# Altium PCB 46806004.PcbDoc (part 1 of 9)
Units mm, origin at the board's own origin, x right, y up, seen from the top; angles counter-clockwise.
Board outline 130 x 105 mm, 8 copper layers (Top Layer, P1-GND, L1-Signal, L2-Signal, L3-Signal, L4-Signal, P2-GND, Bottom Layer), stack 1.63 mm thick; 796 components, 496 nets, 2808 pads, 1195 vias.
Unrouted connection lines stored in the file: 1.
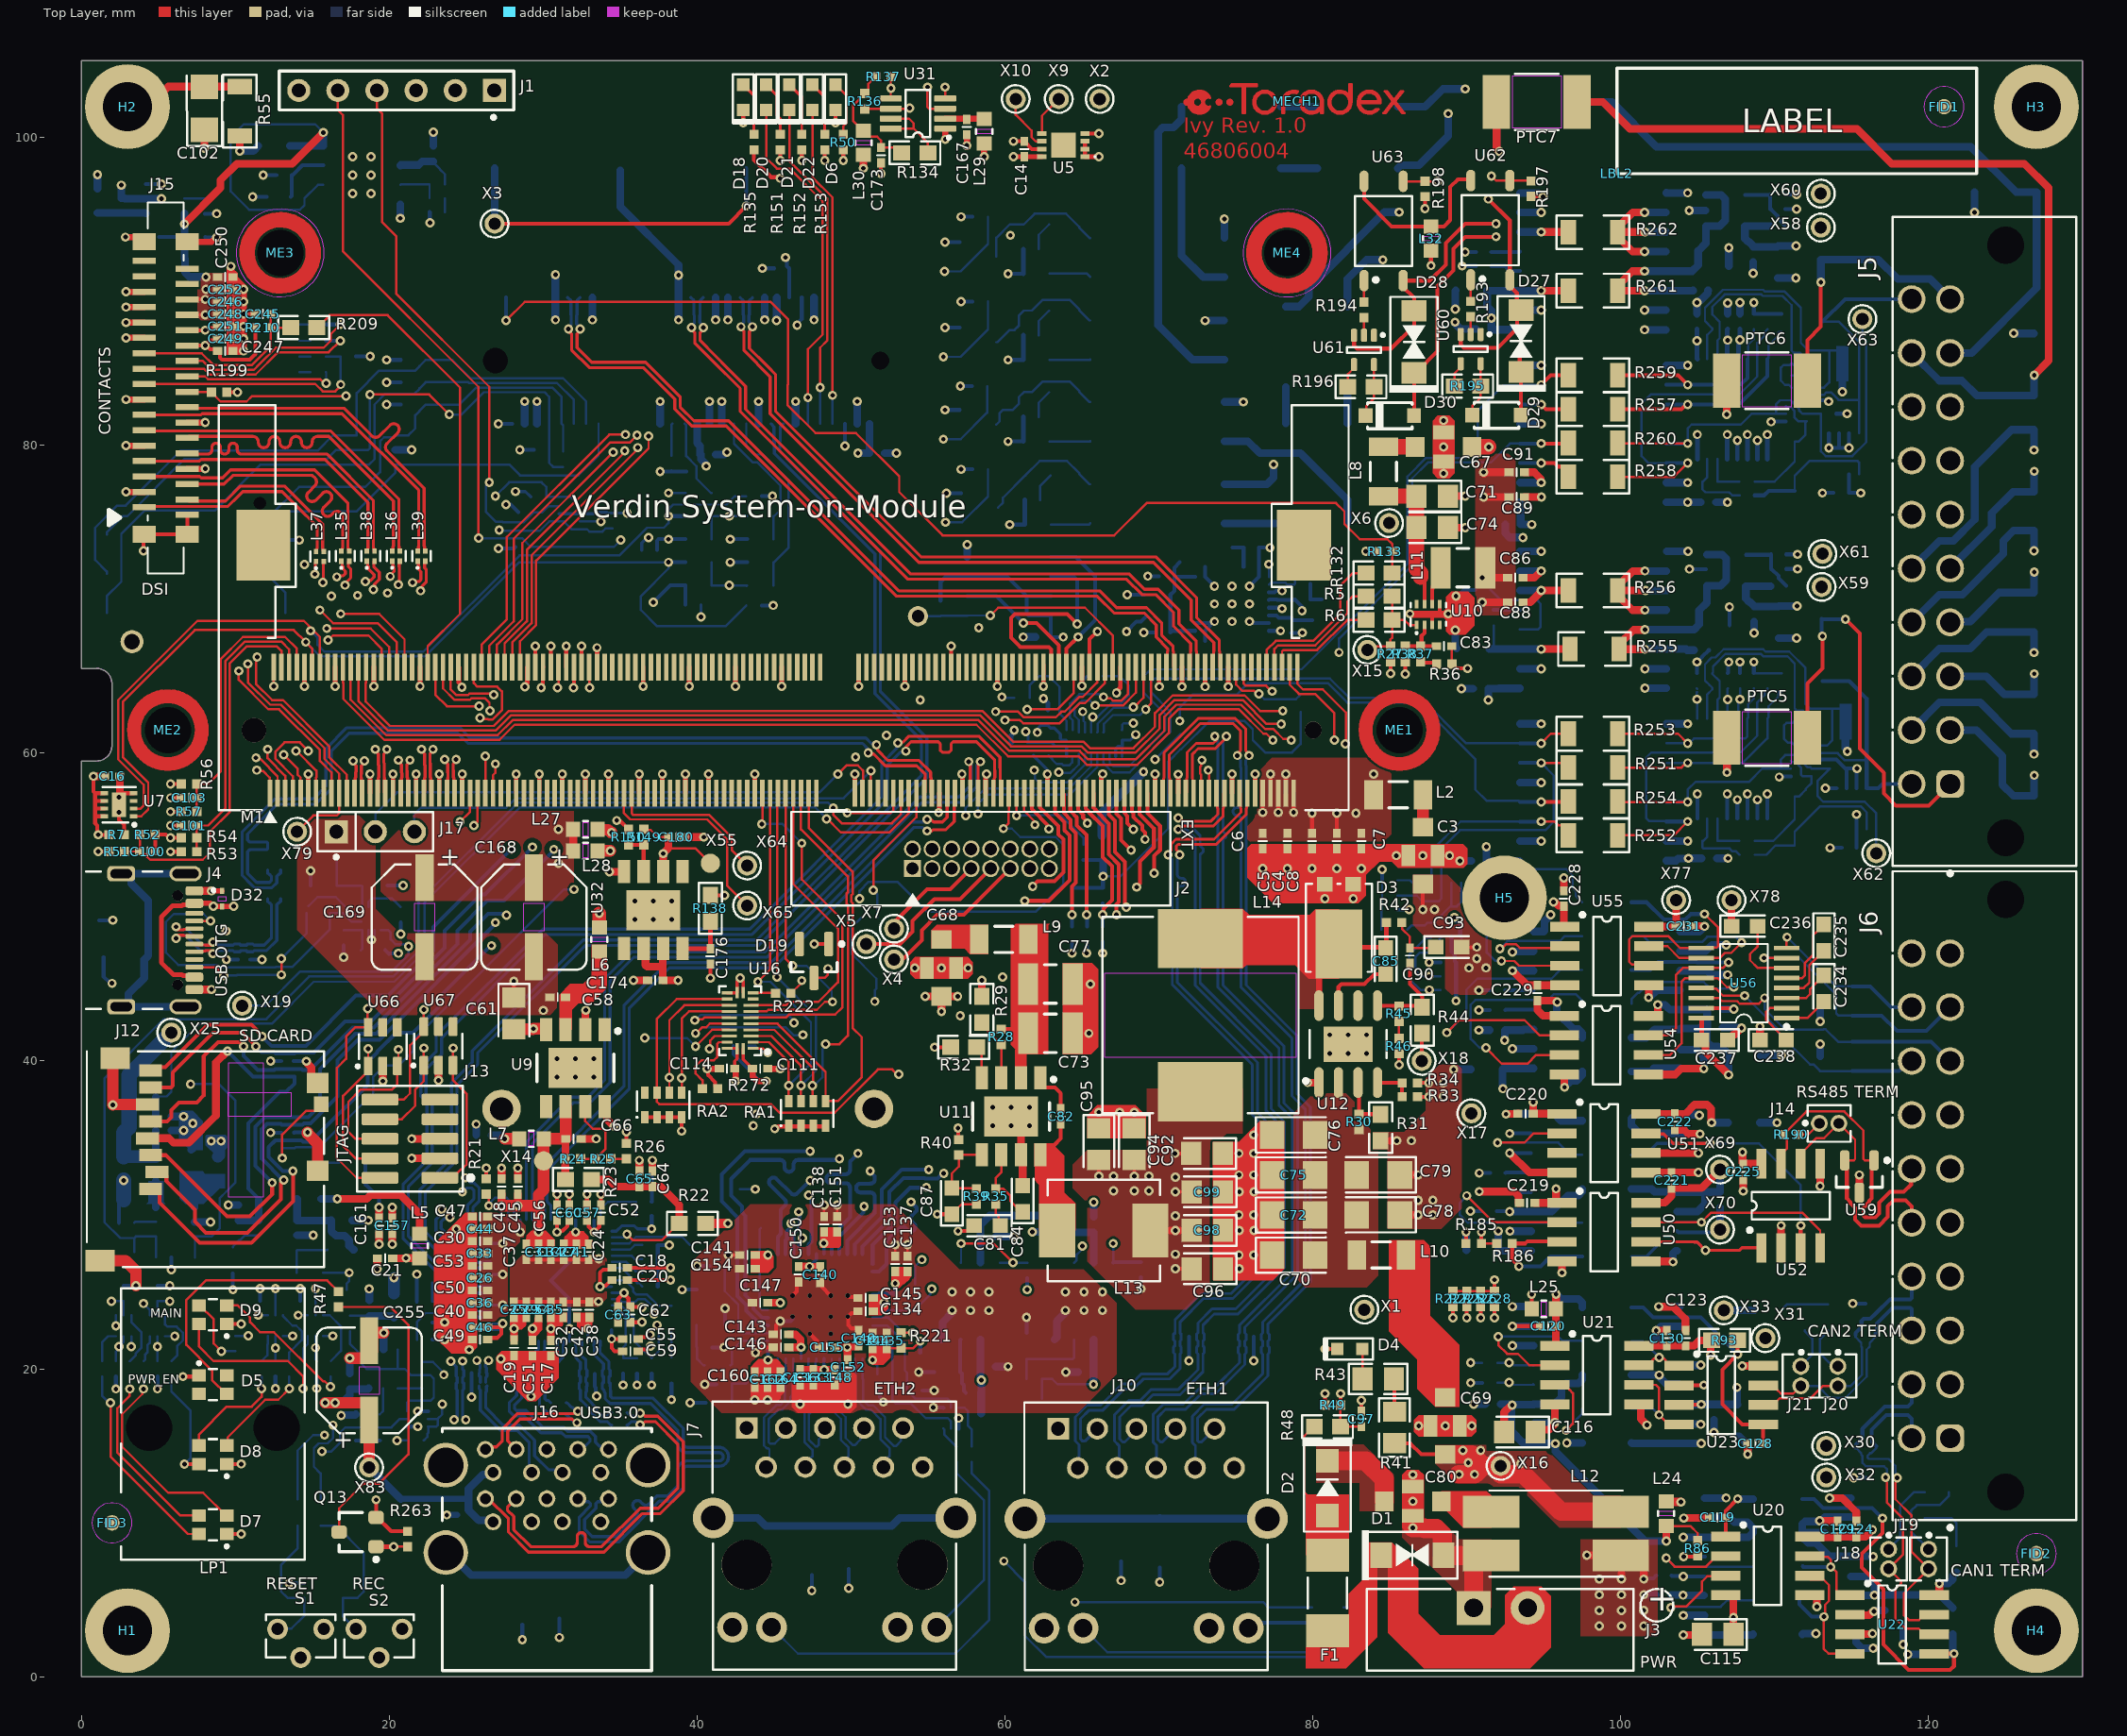
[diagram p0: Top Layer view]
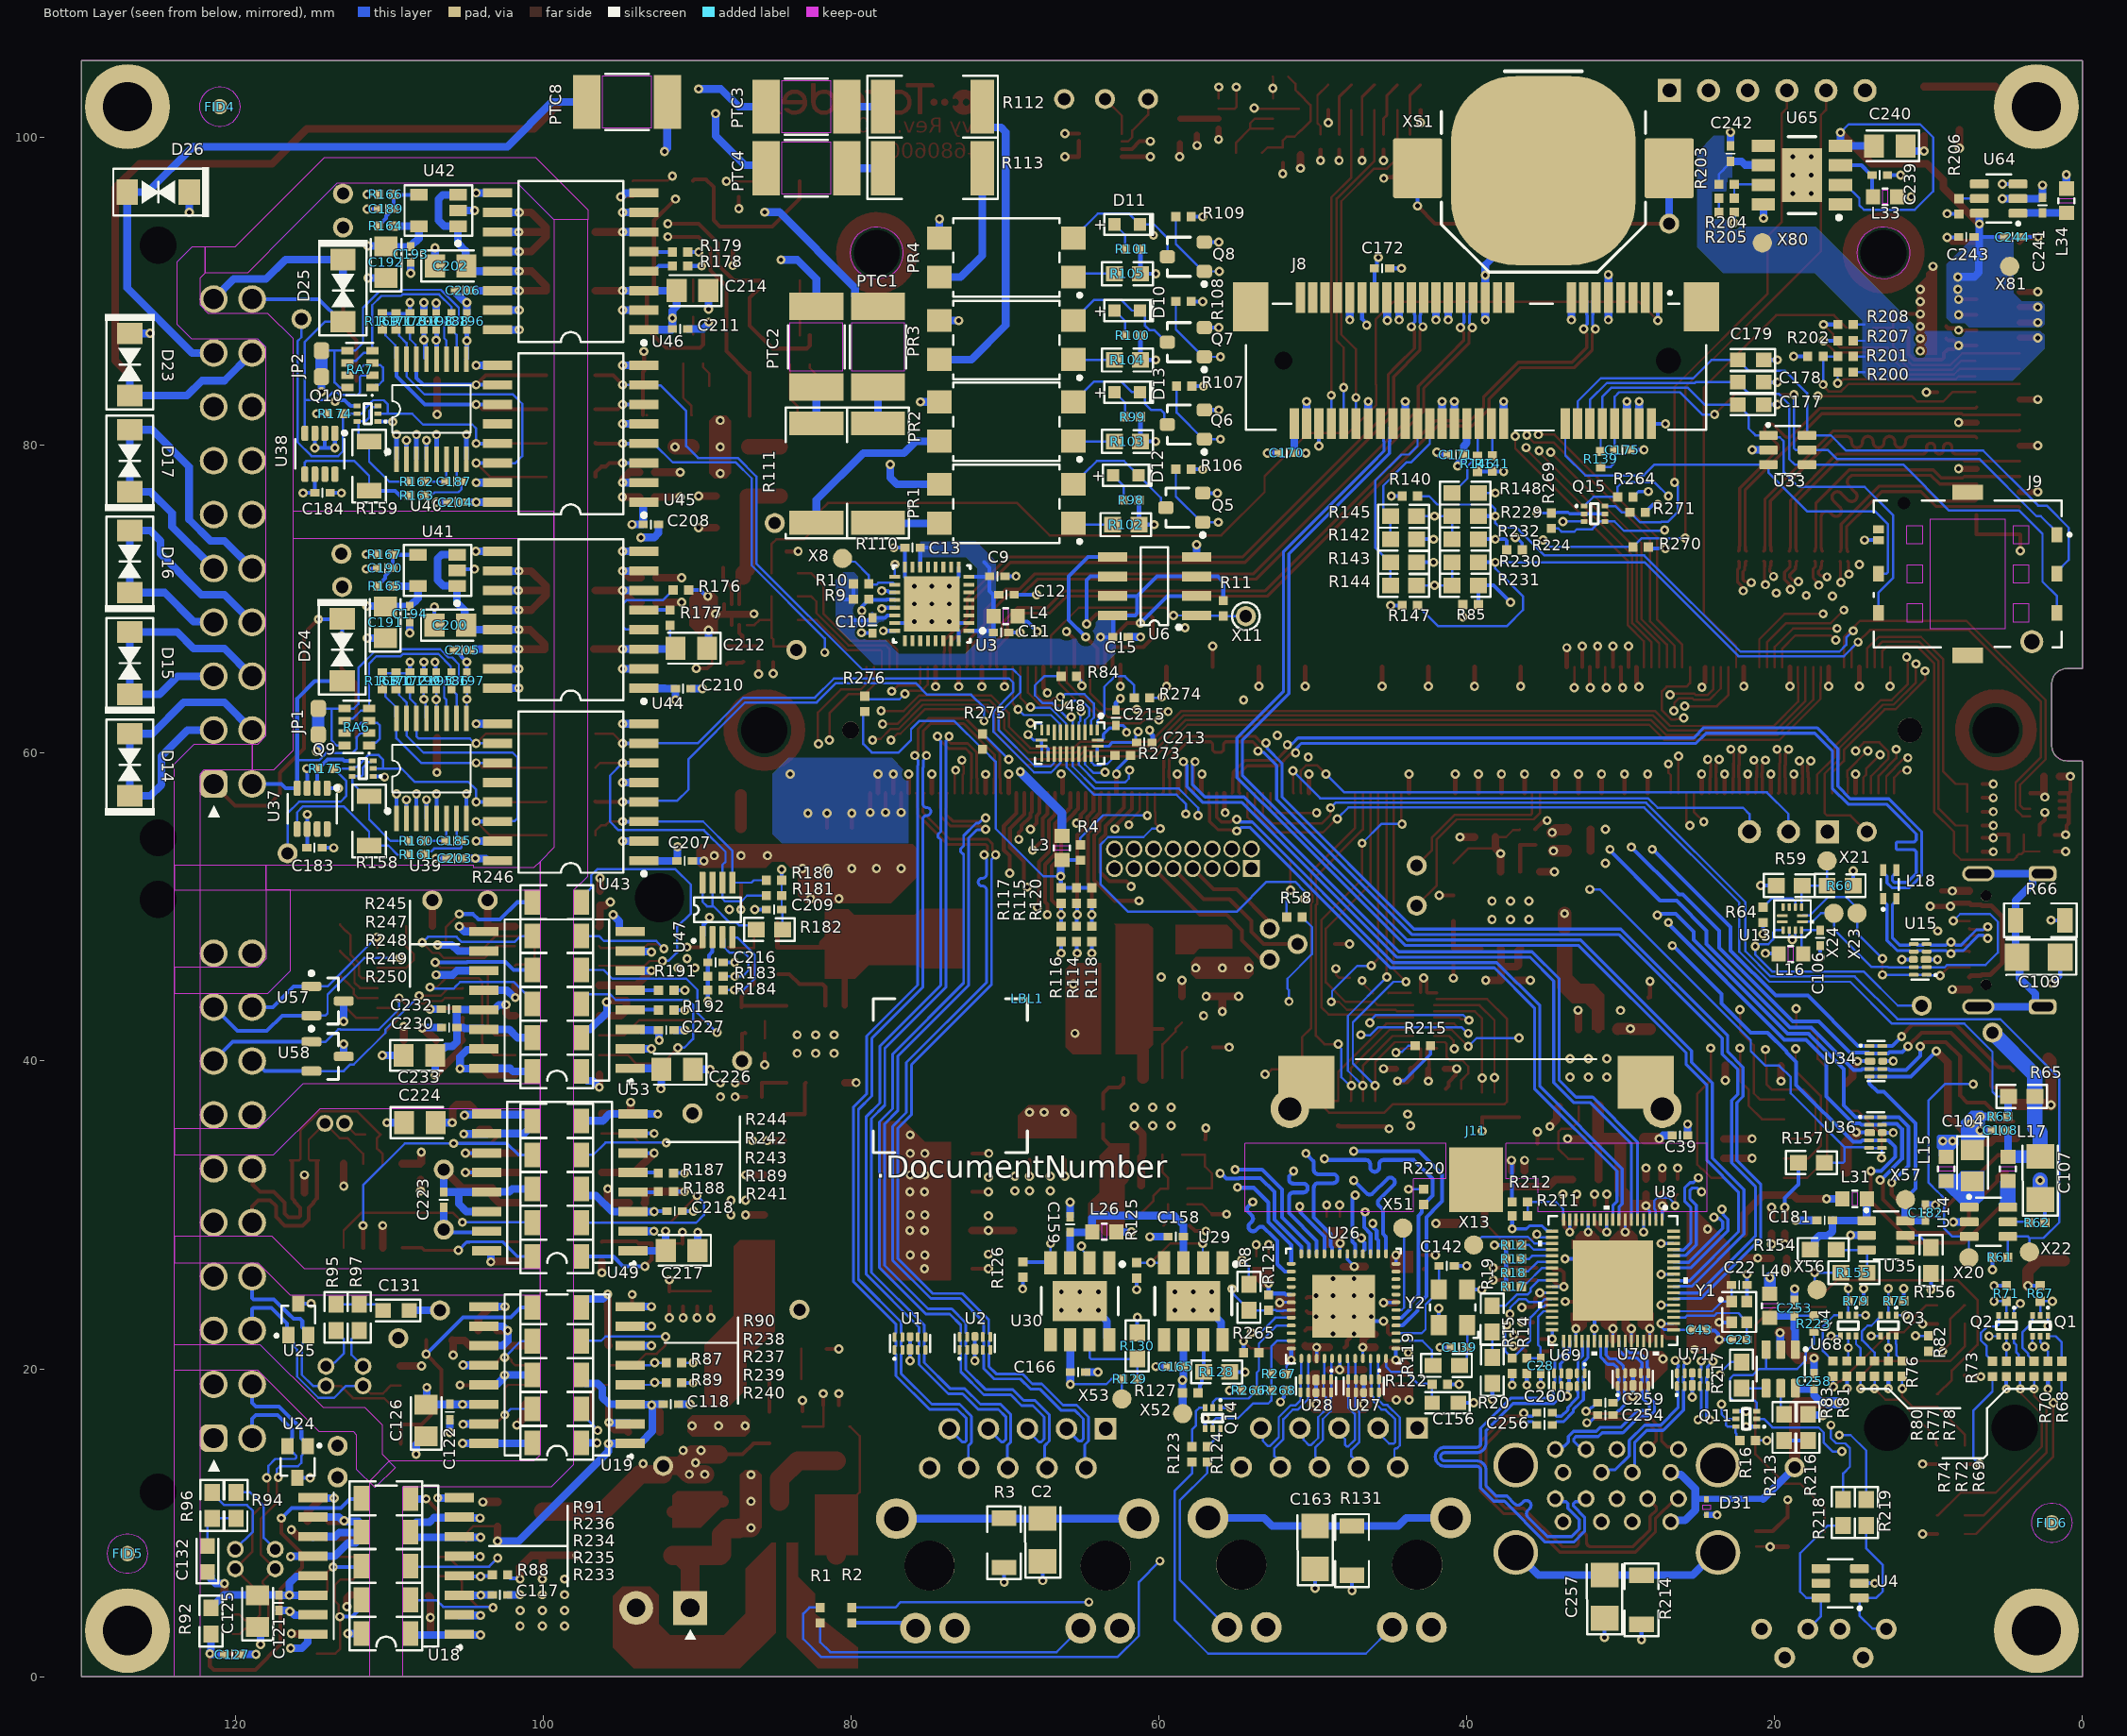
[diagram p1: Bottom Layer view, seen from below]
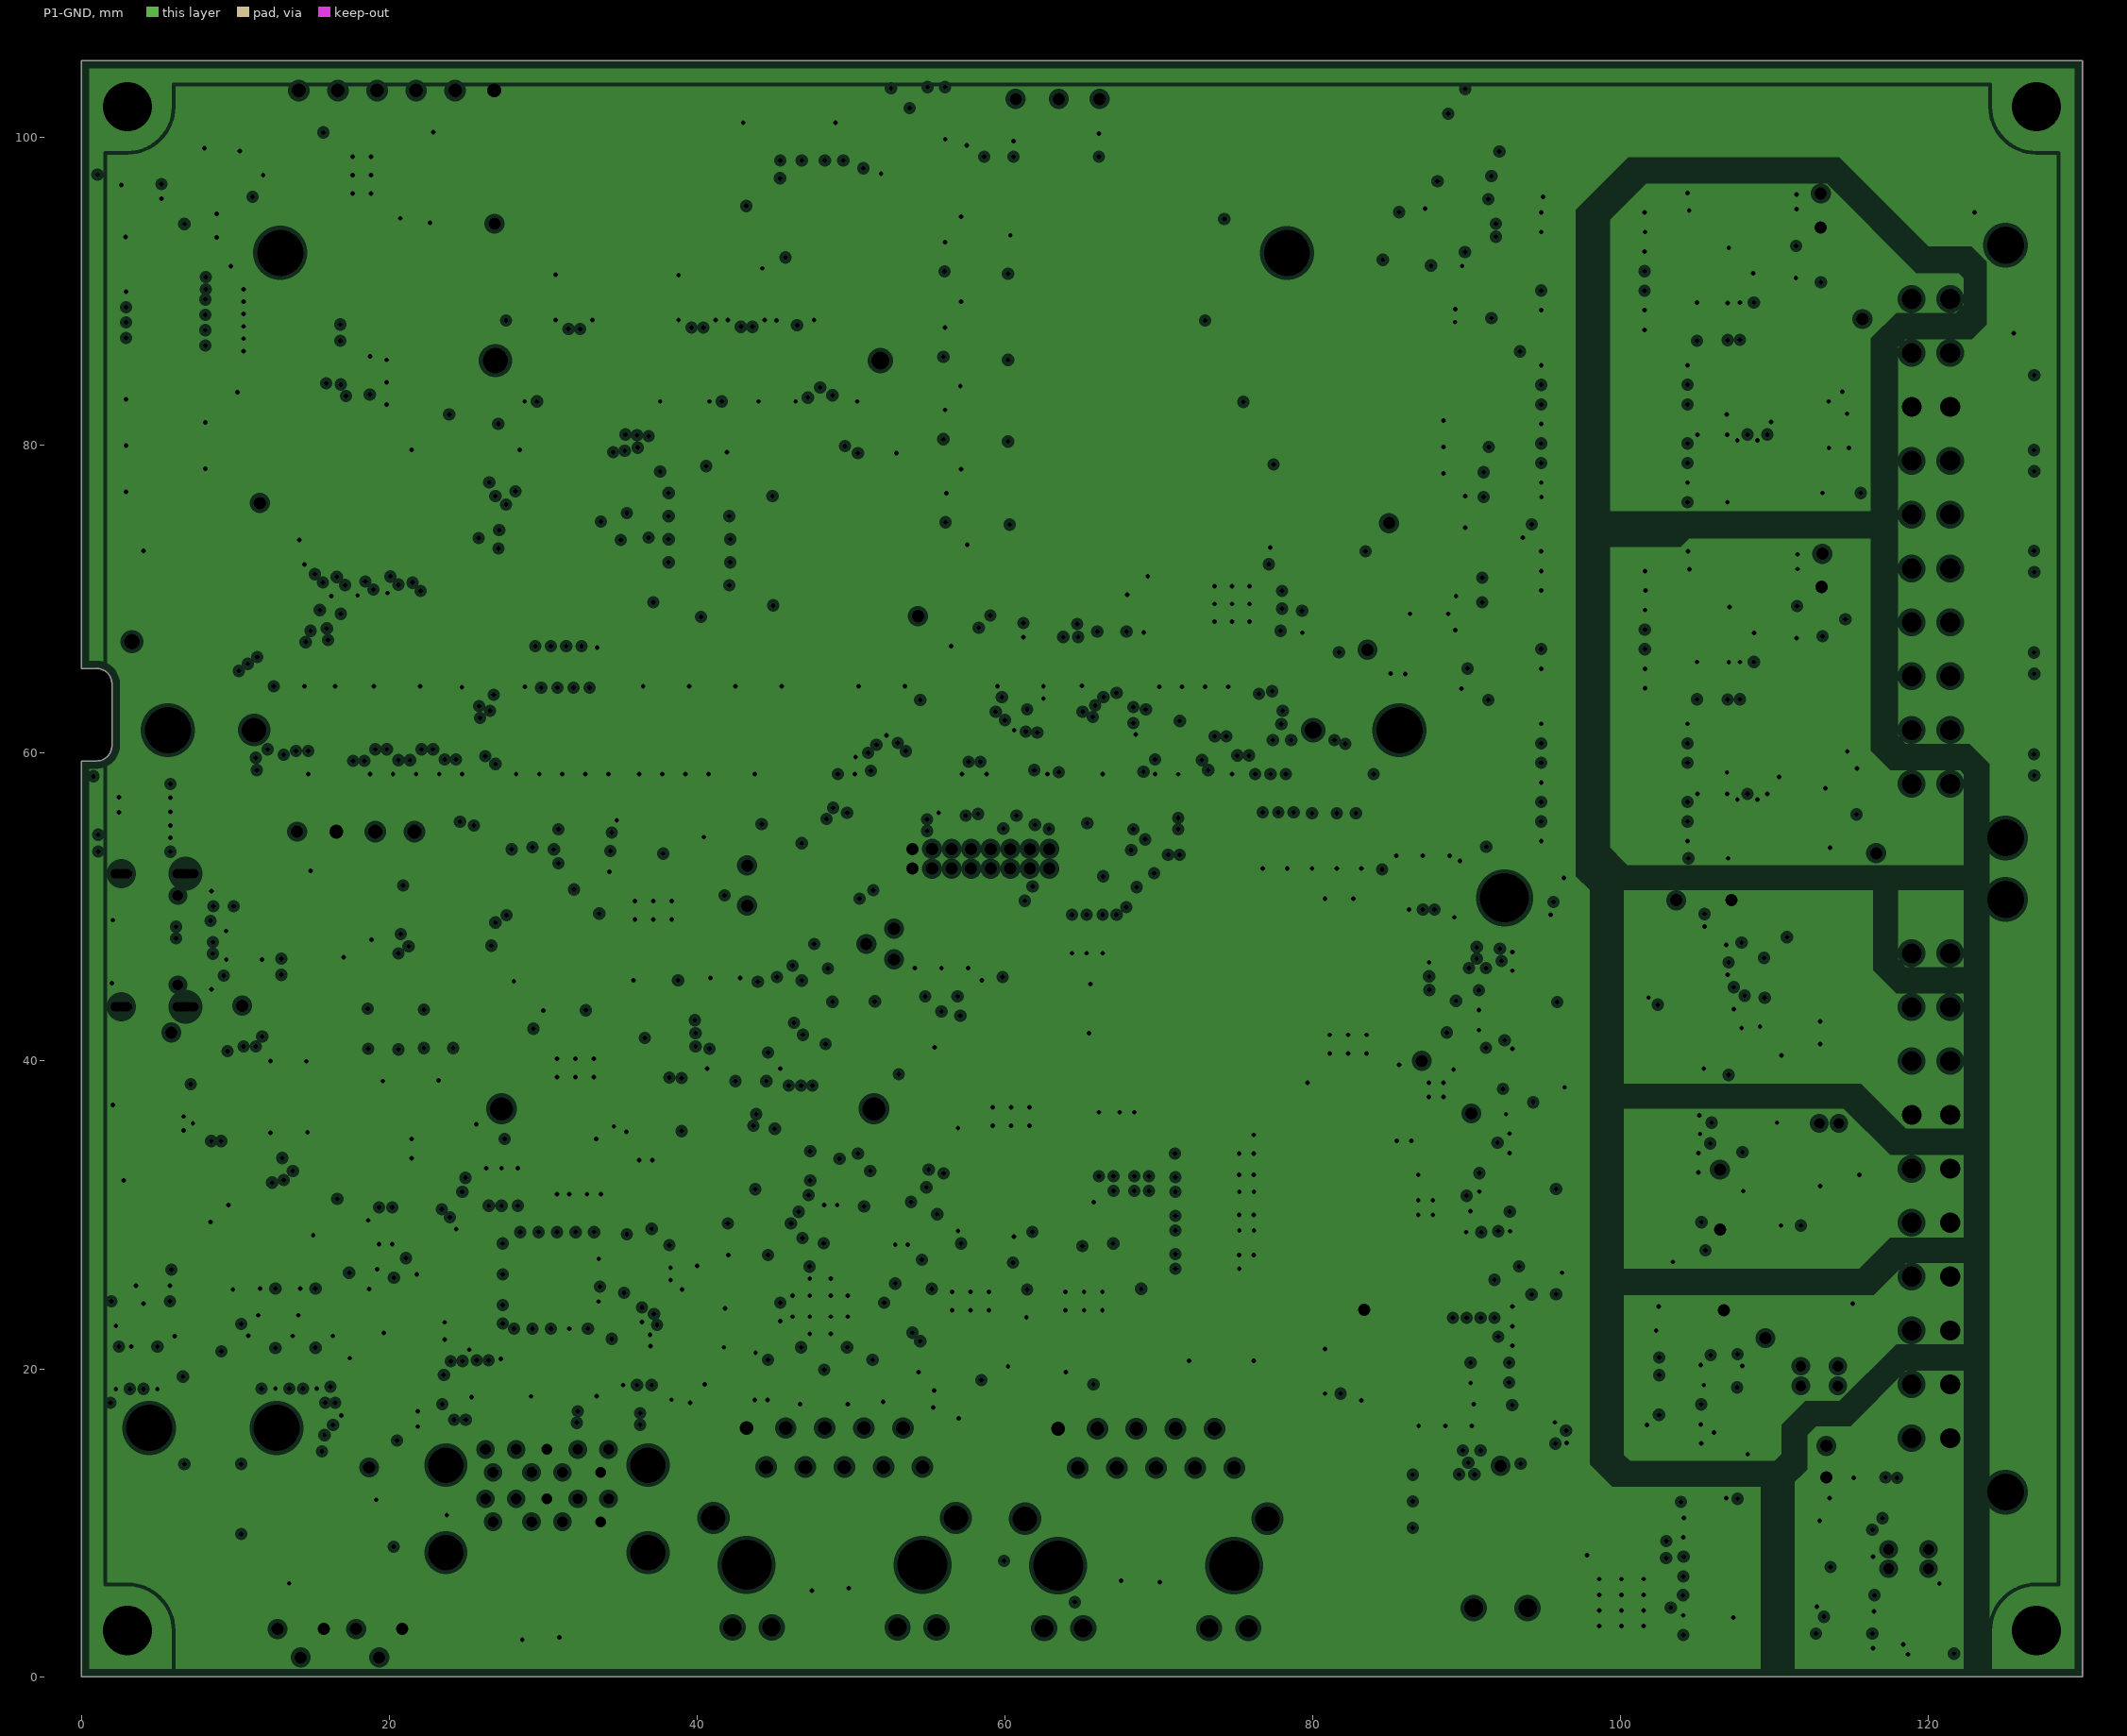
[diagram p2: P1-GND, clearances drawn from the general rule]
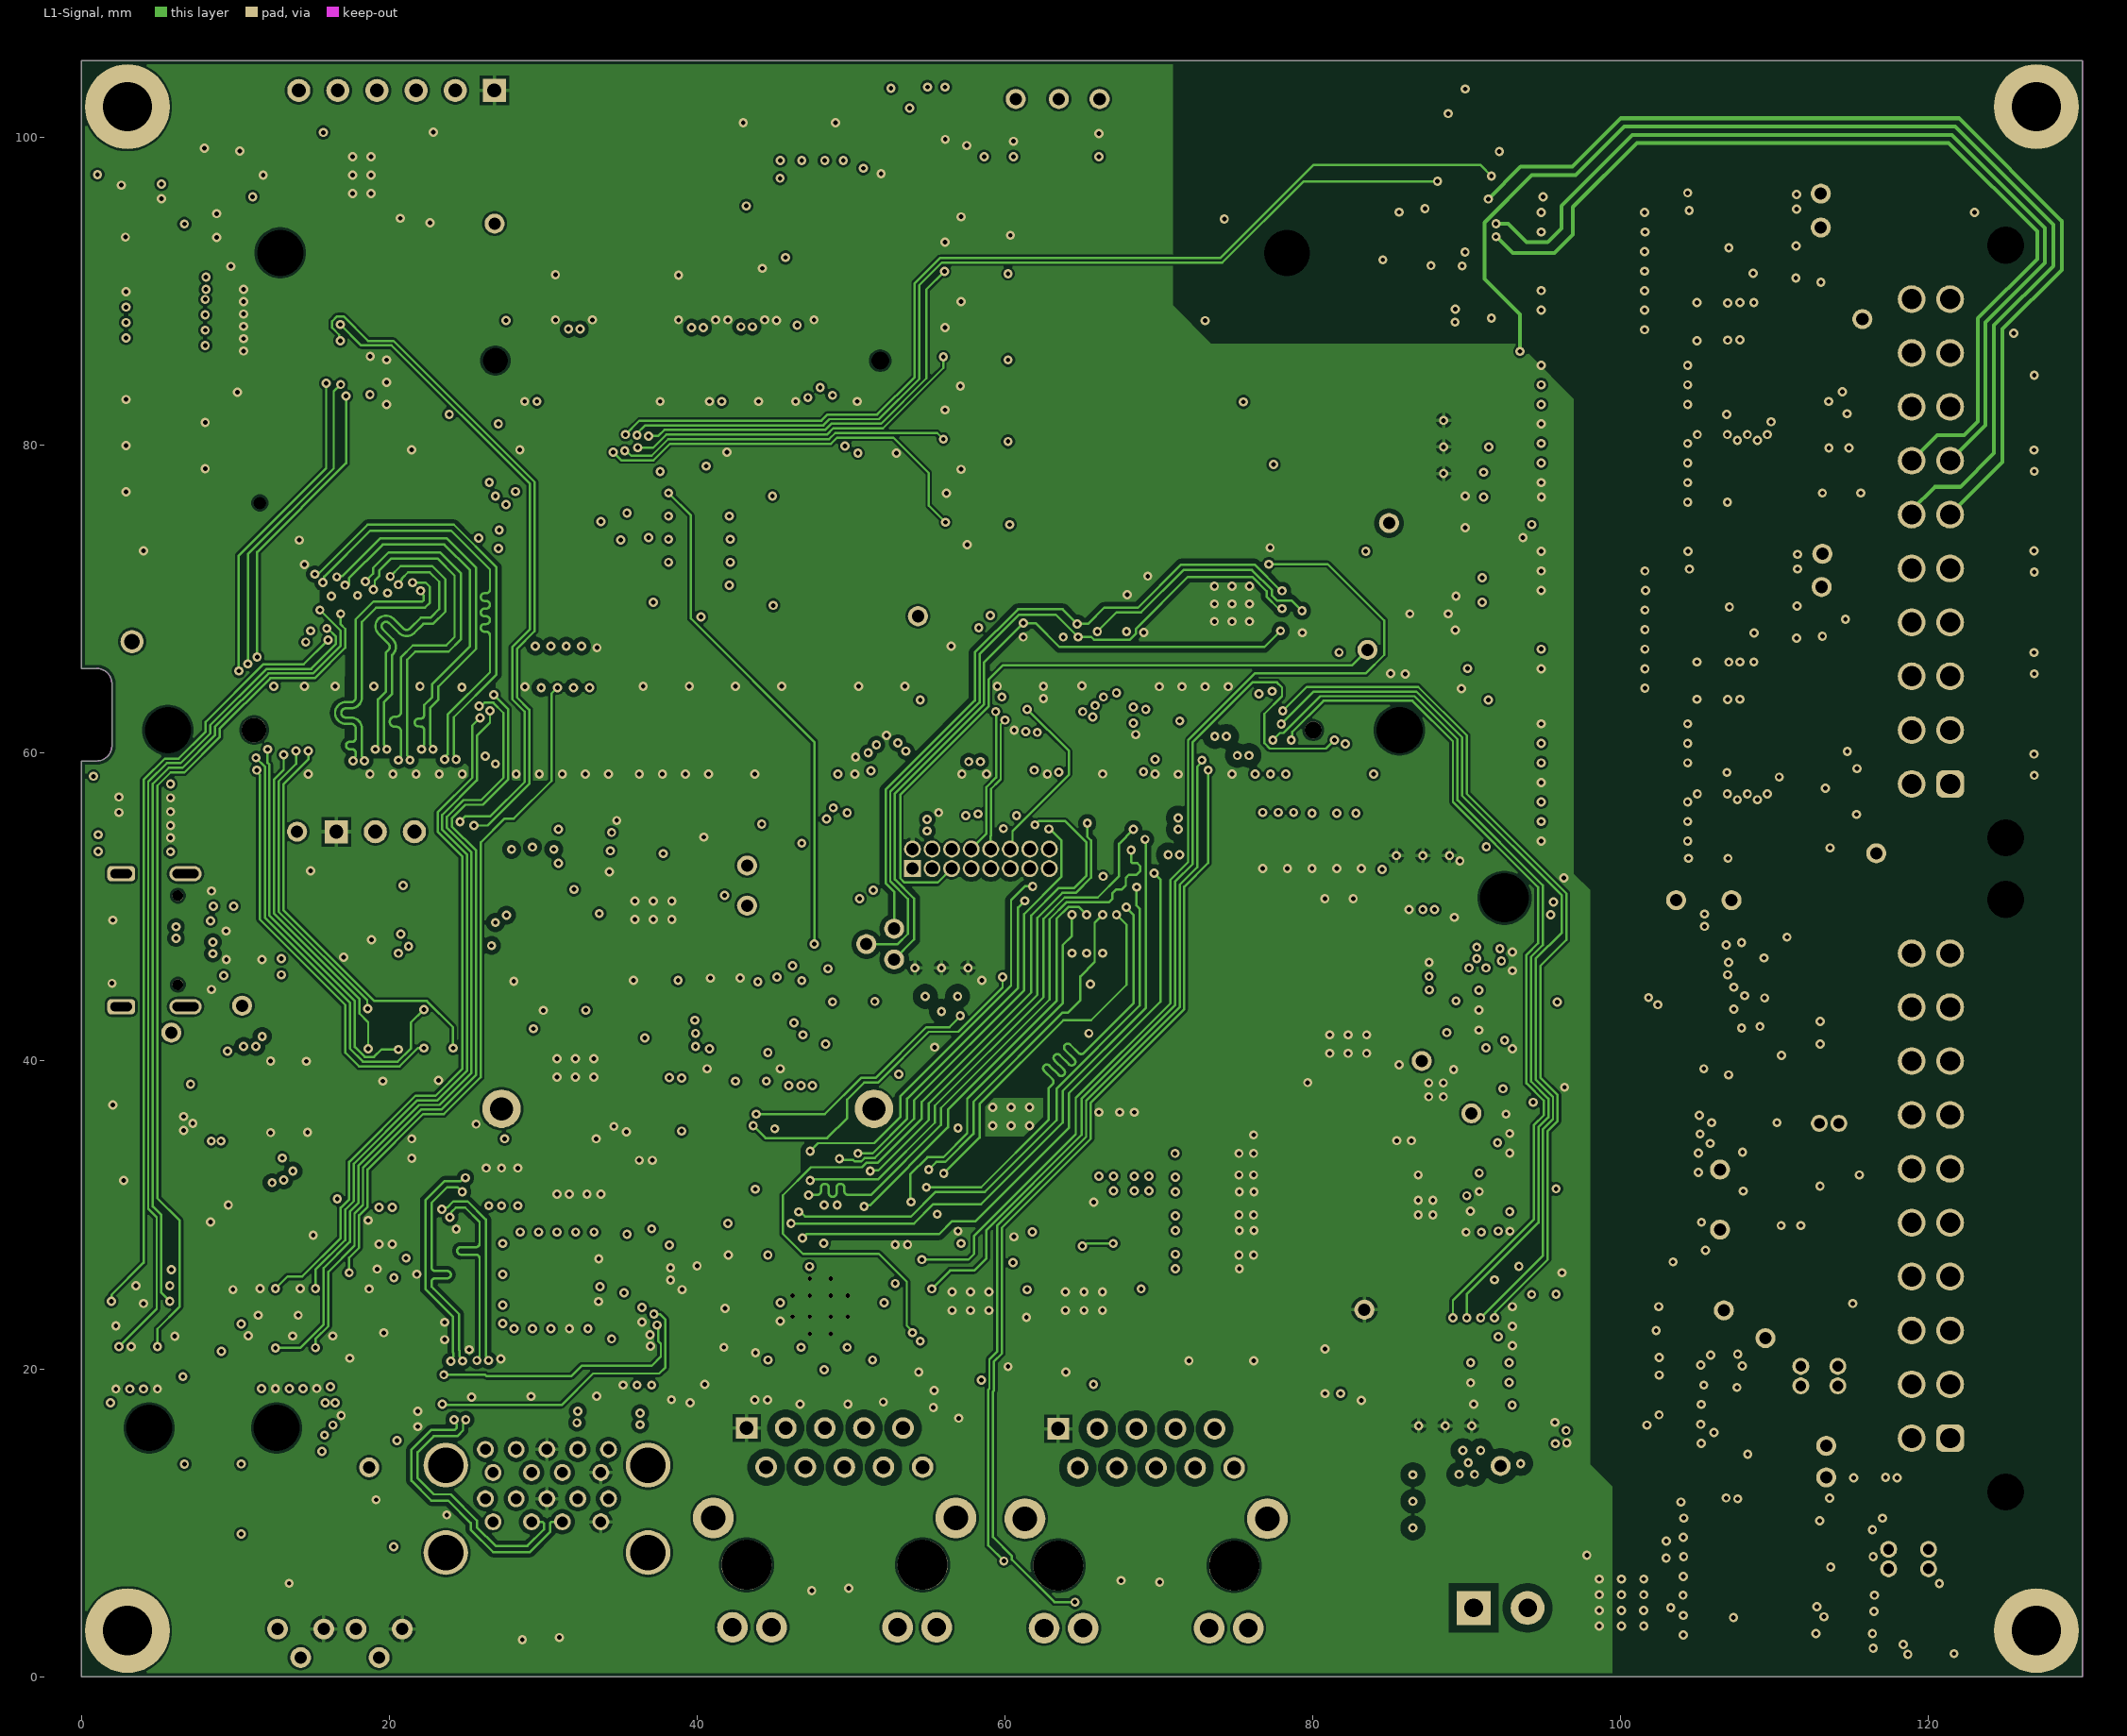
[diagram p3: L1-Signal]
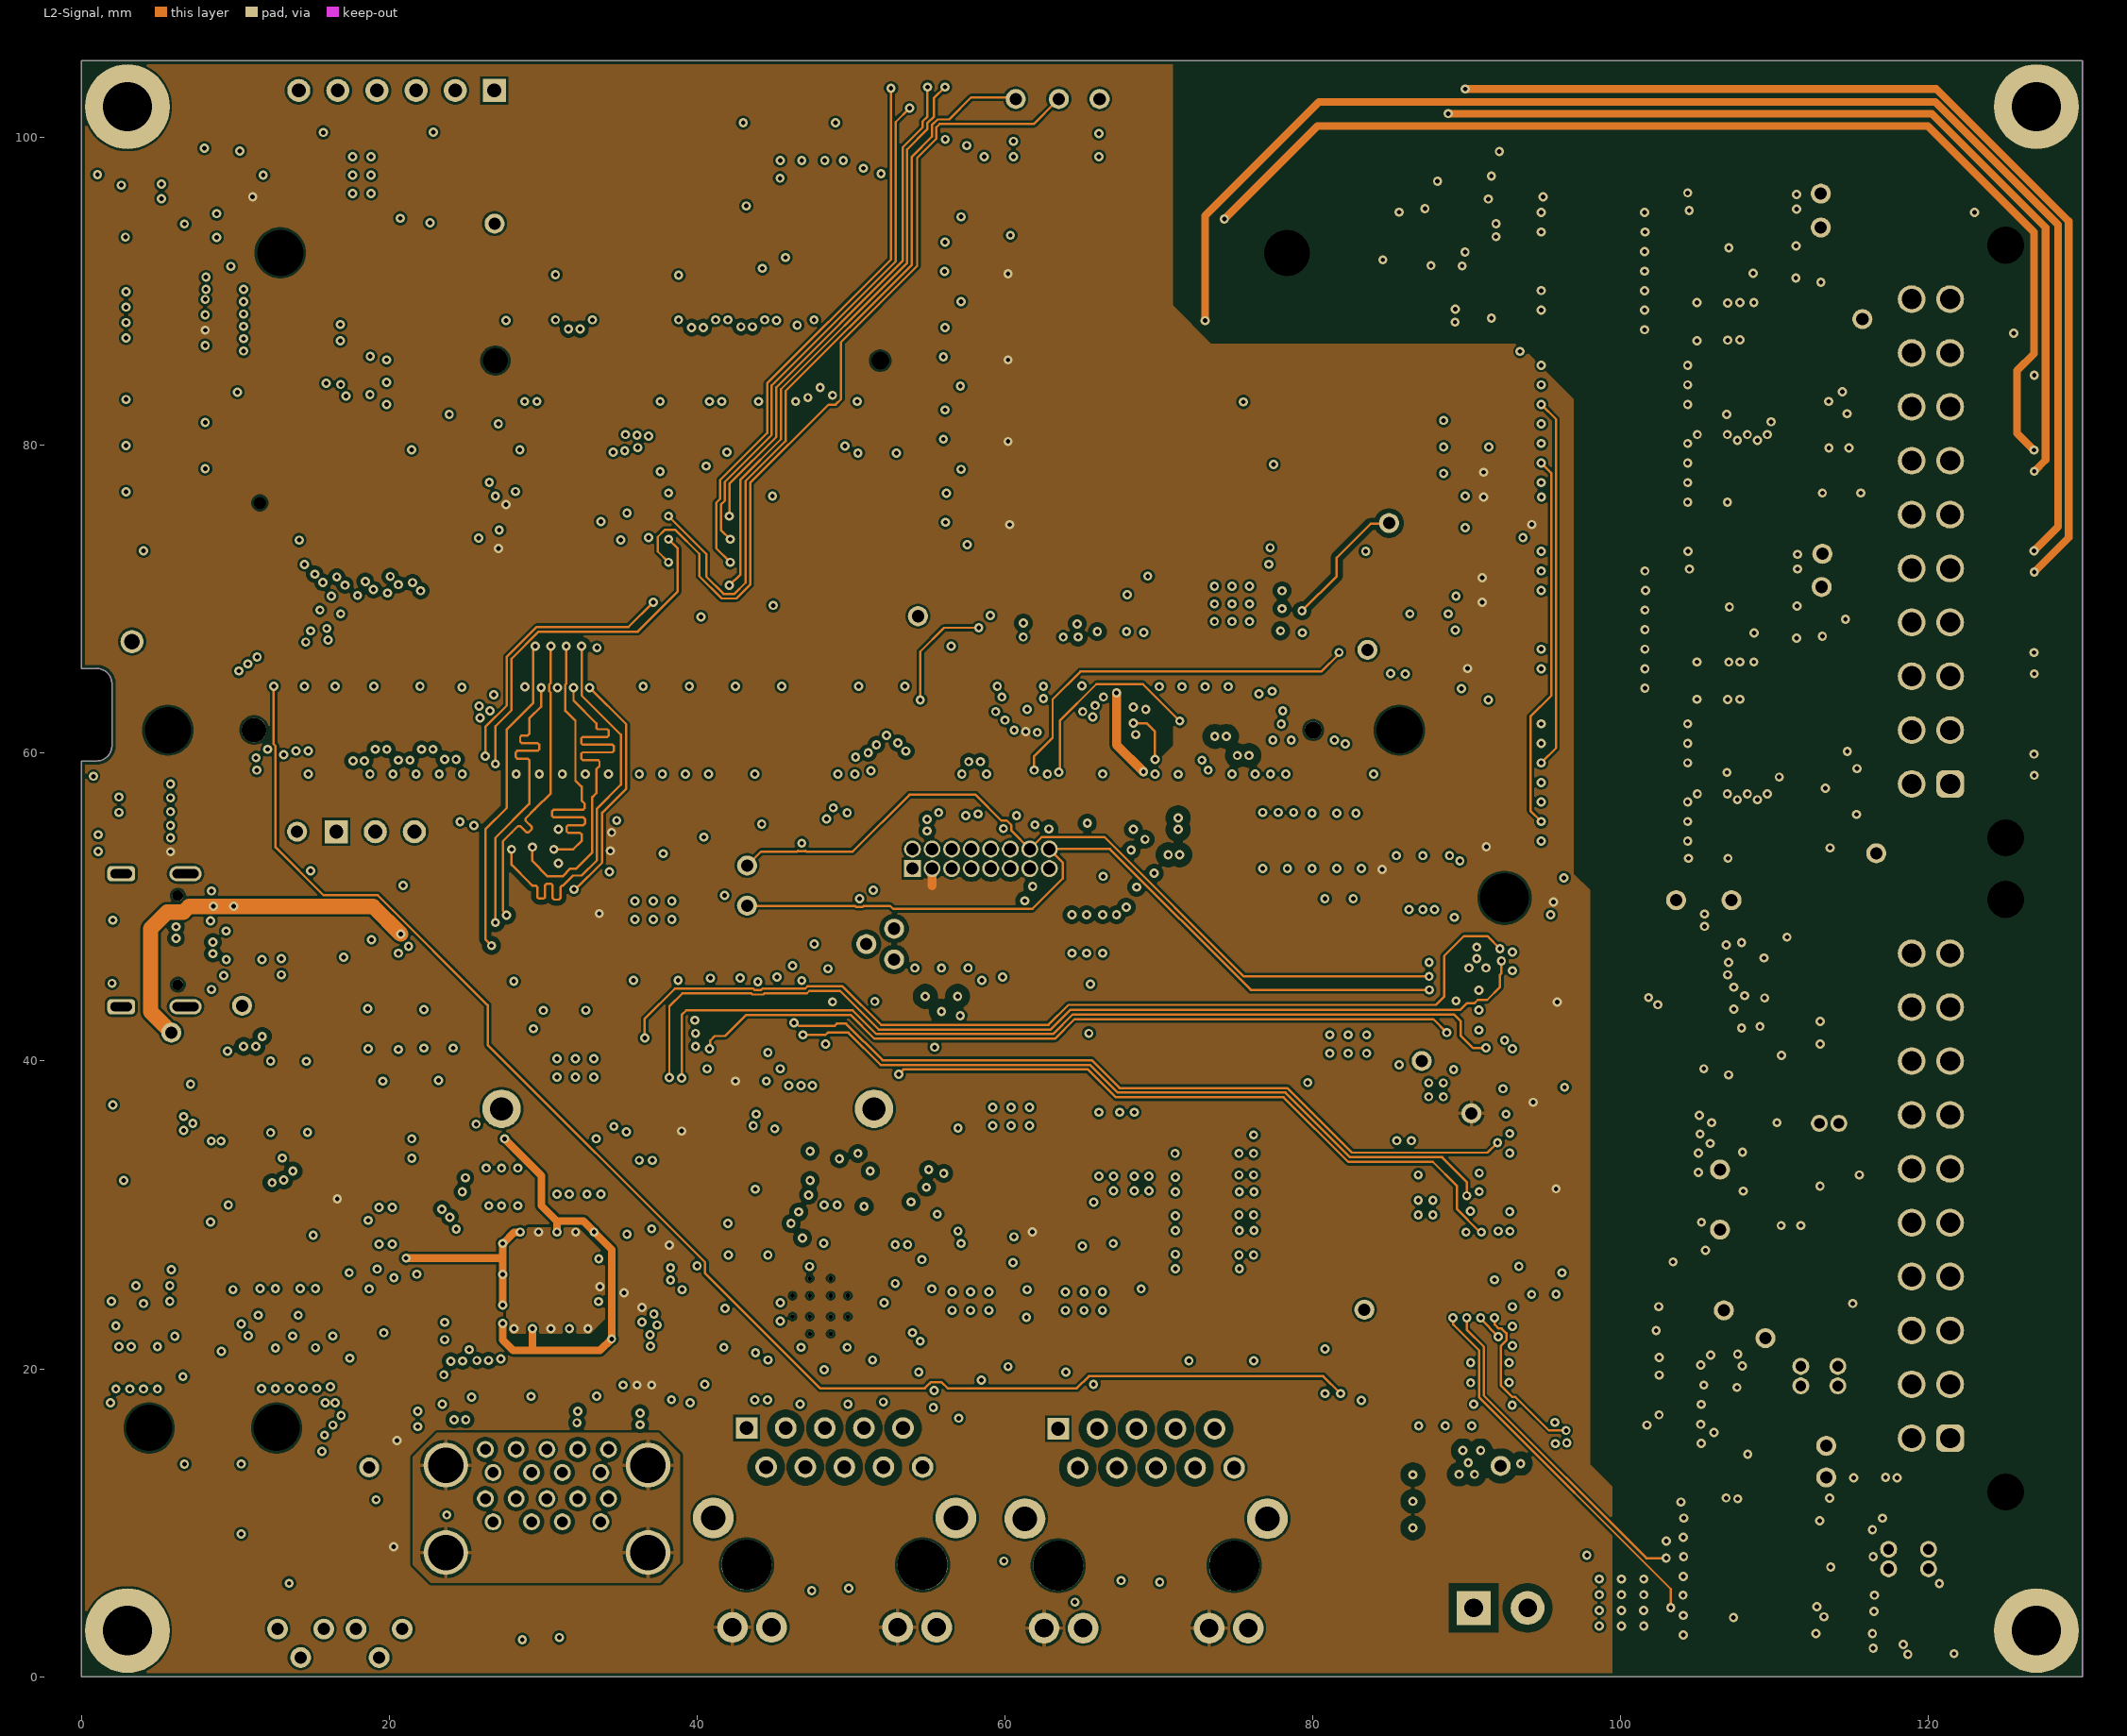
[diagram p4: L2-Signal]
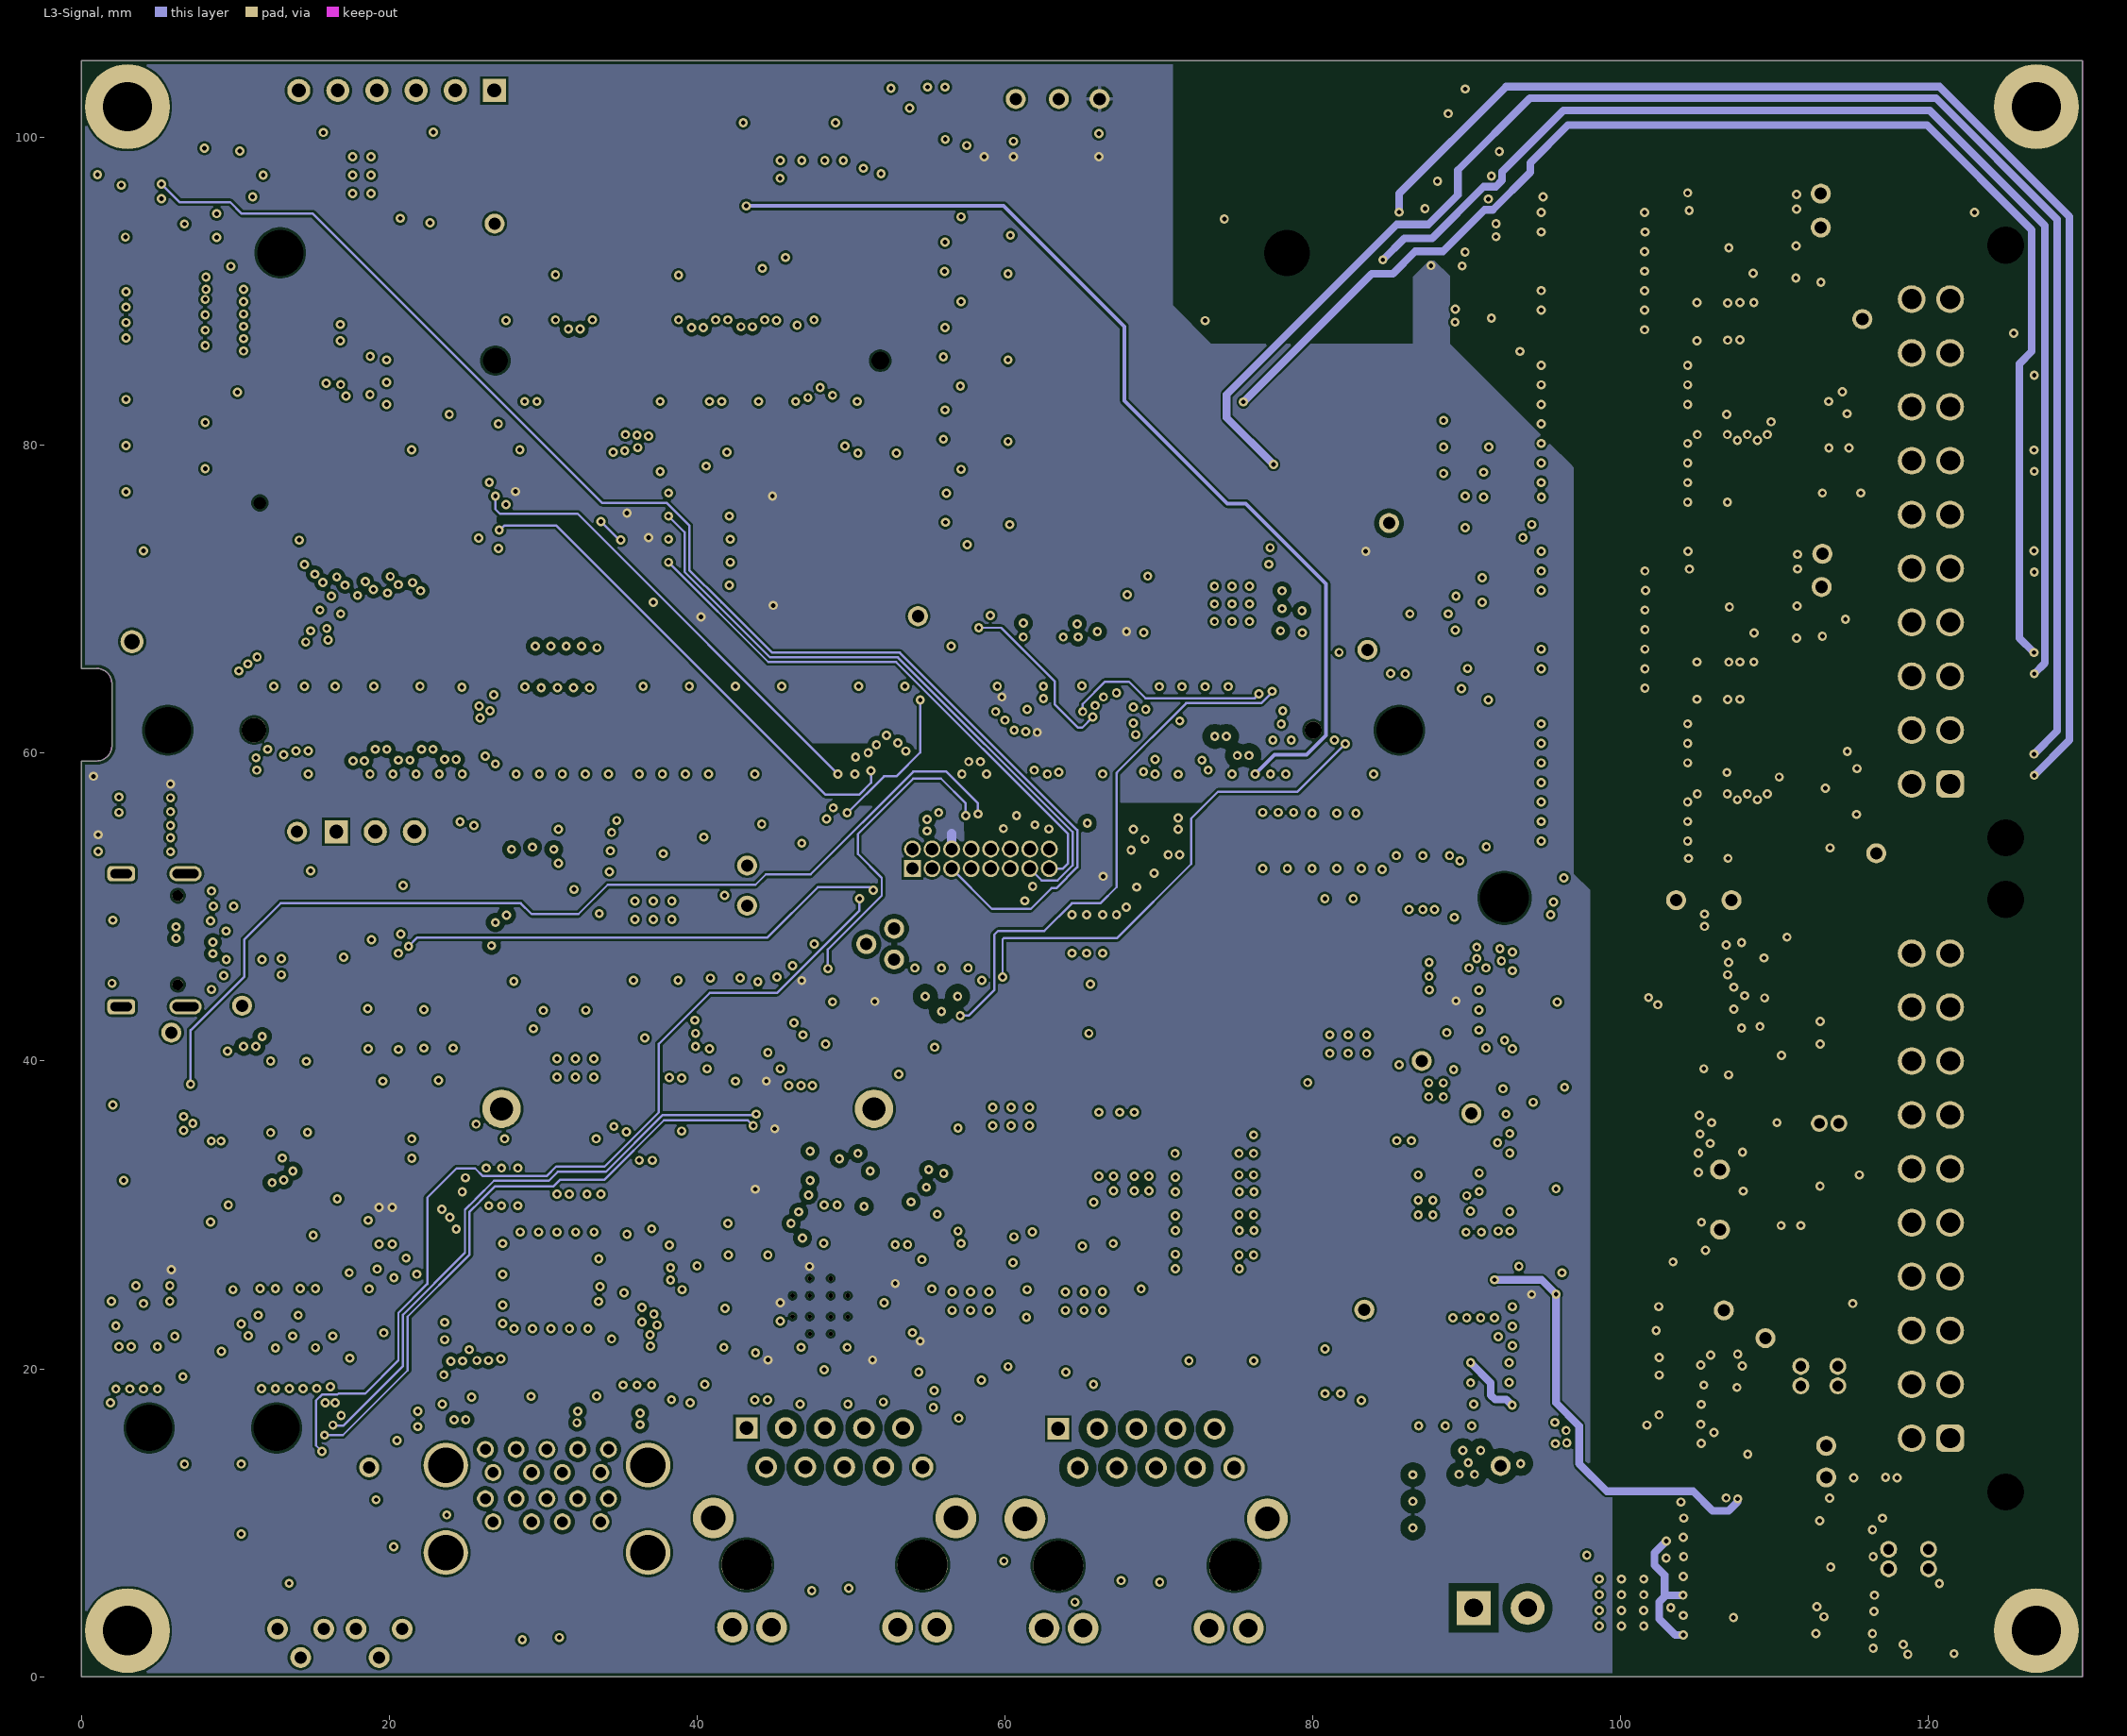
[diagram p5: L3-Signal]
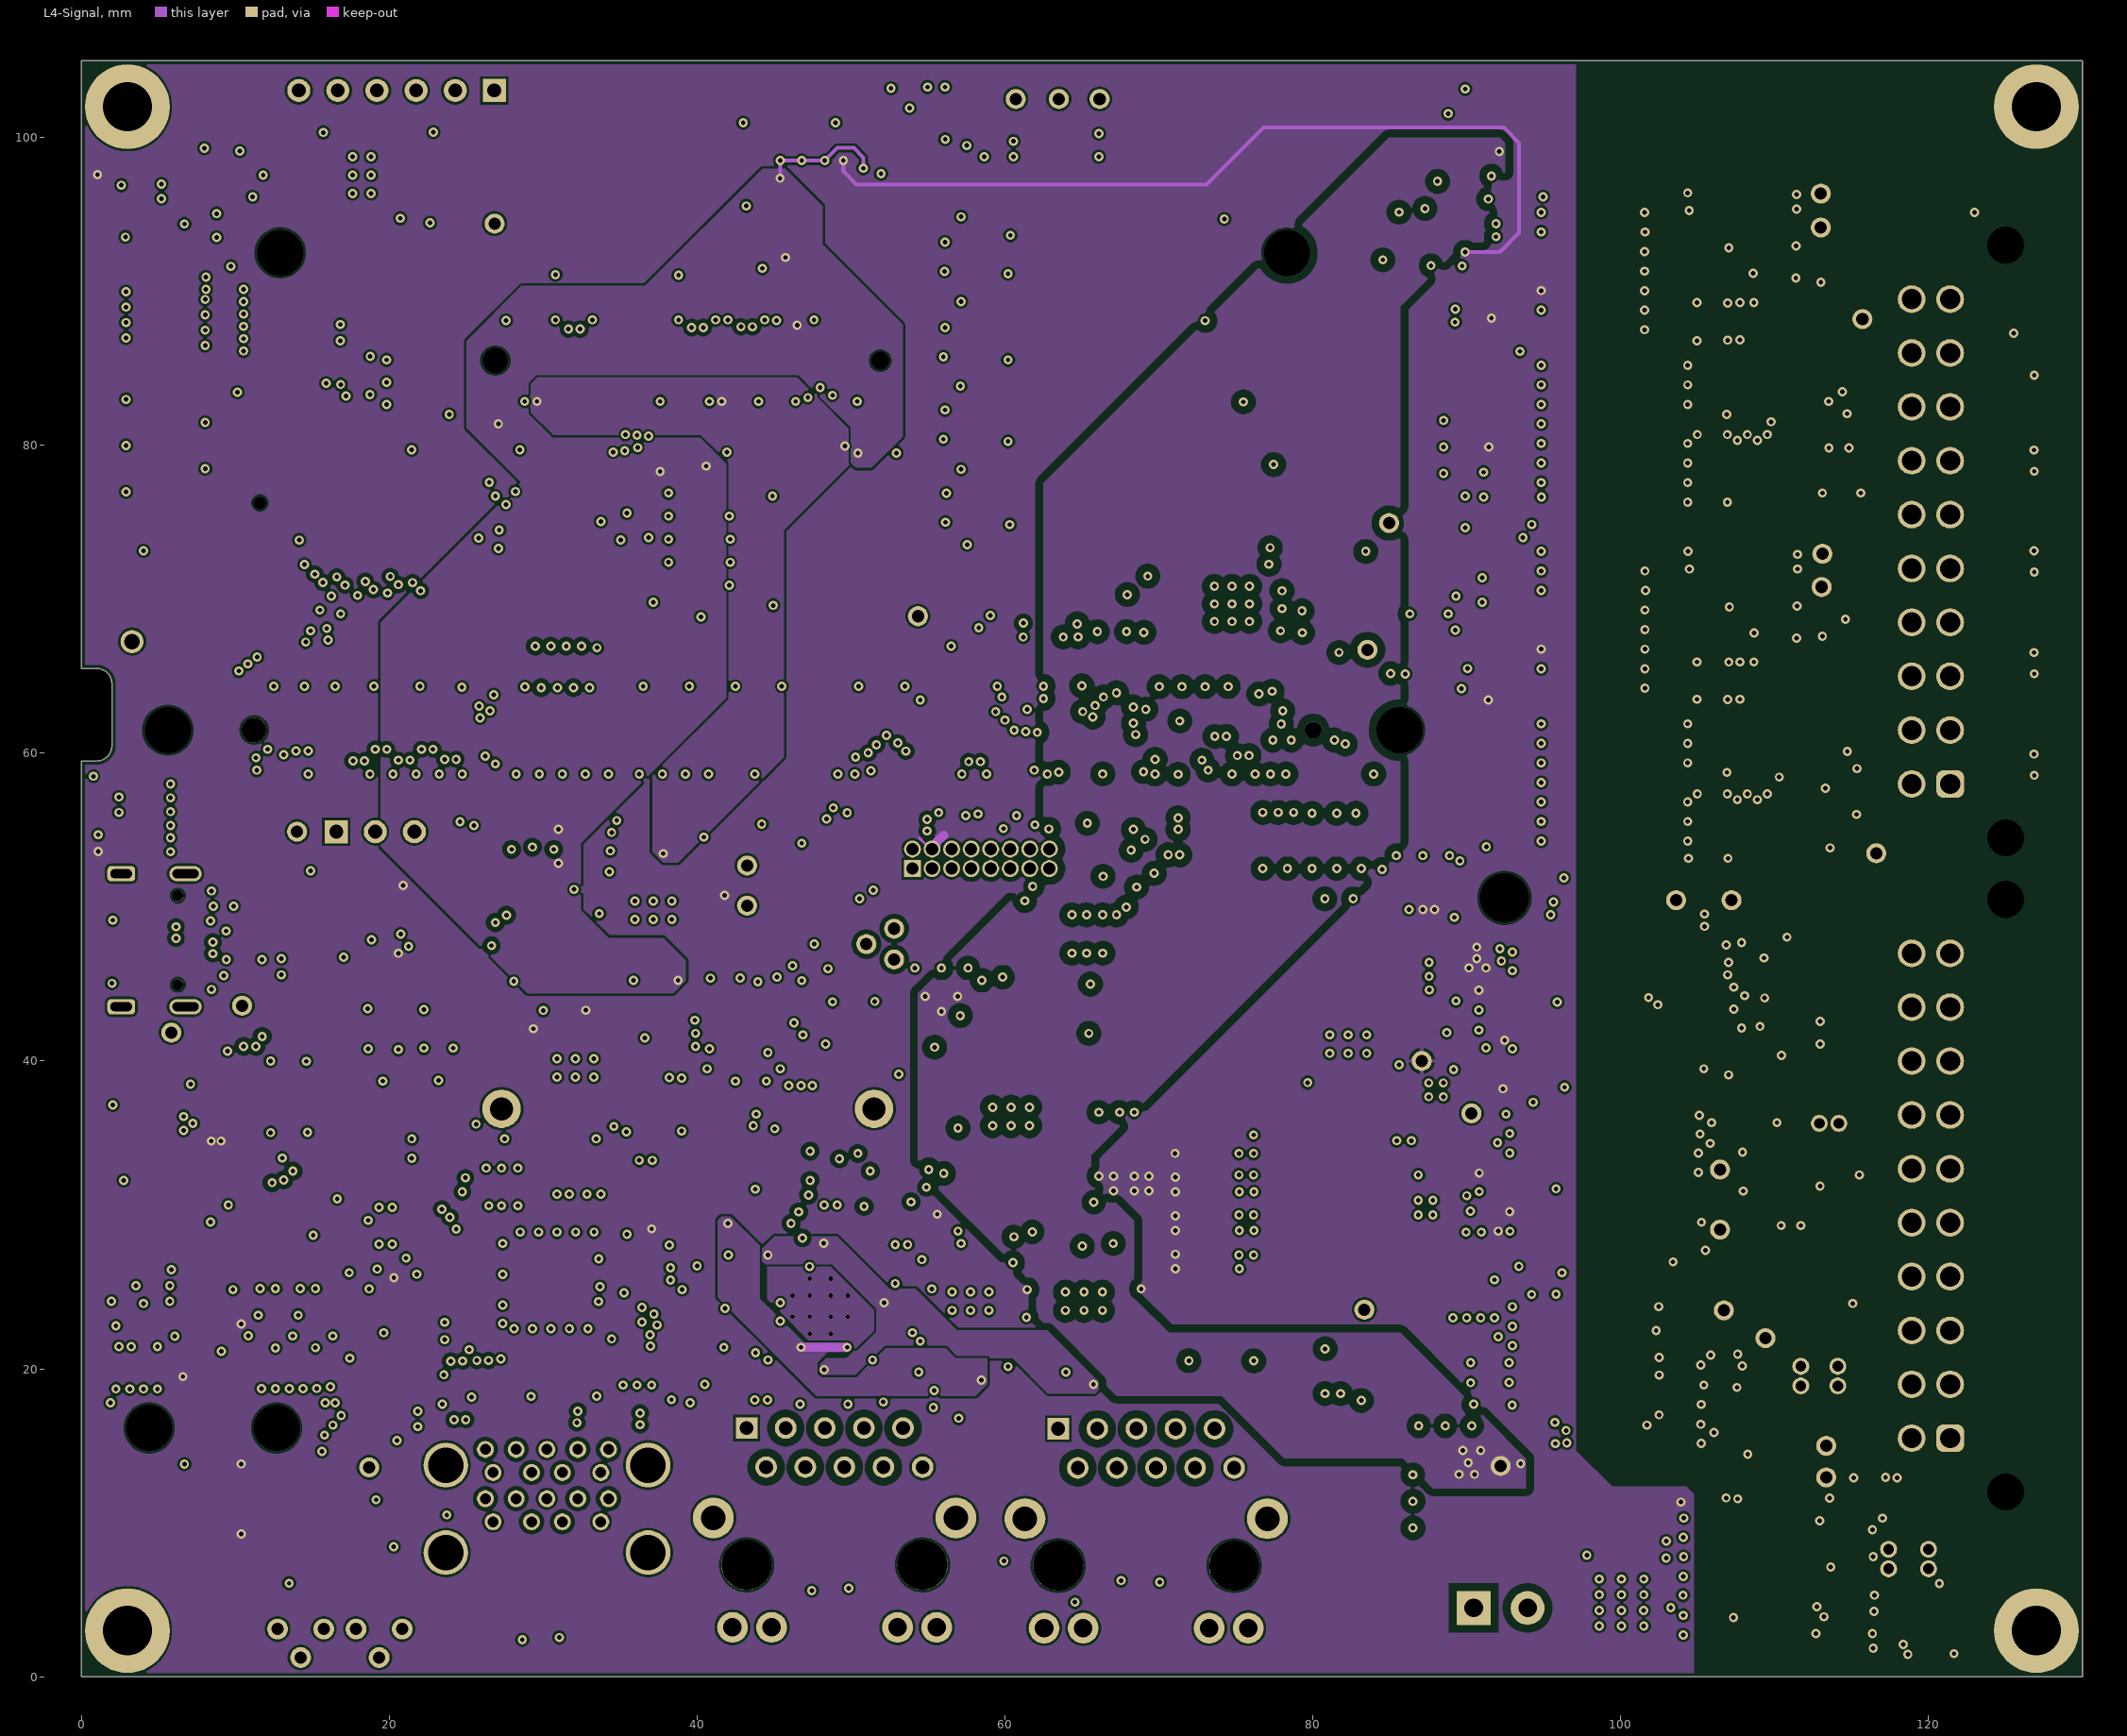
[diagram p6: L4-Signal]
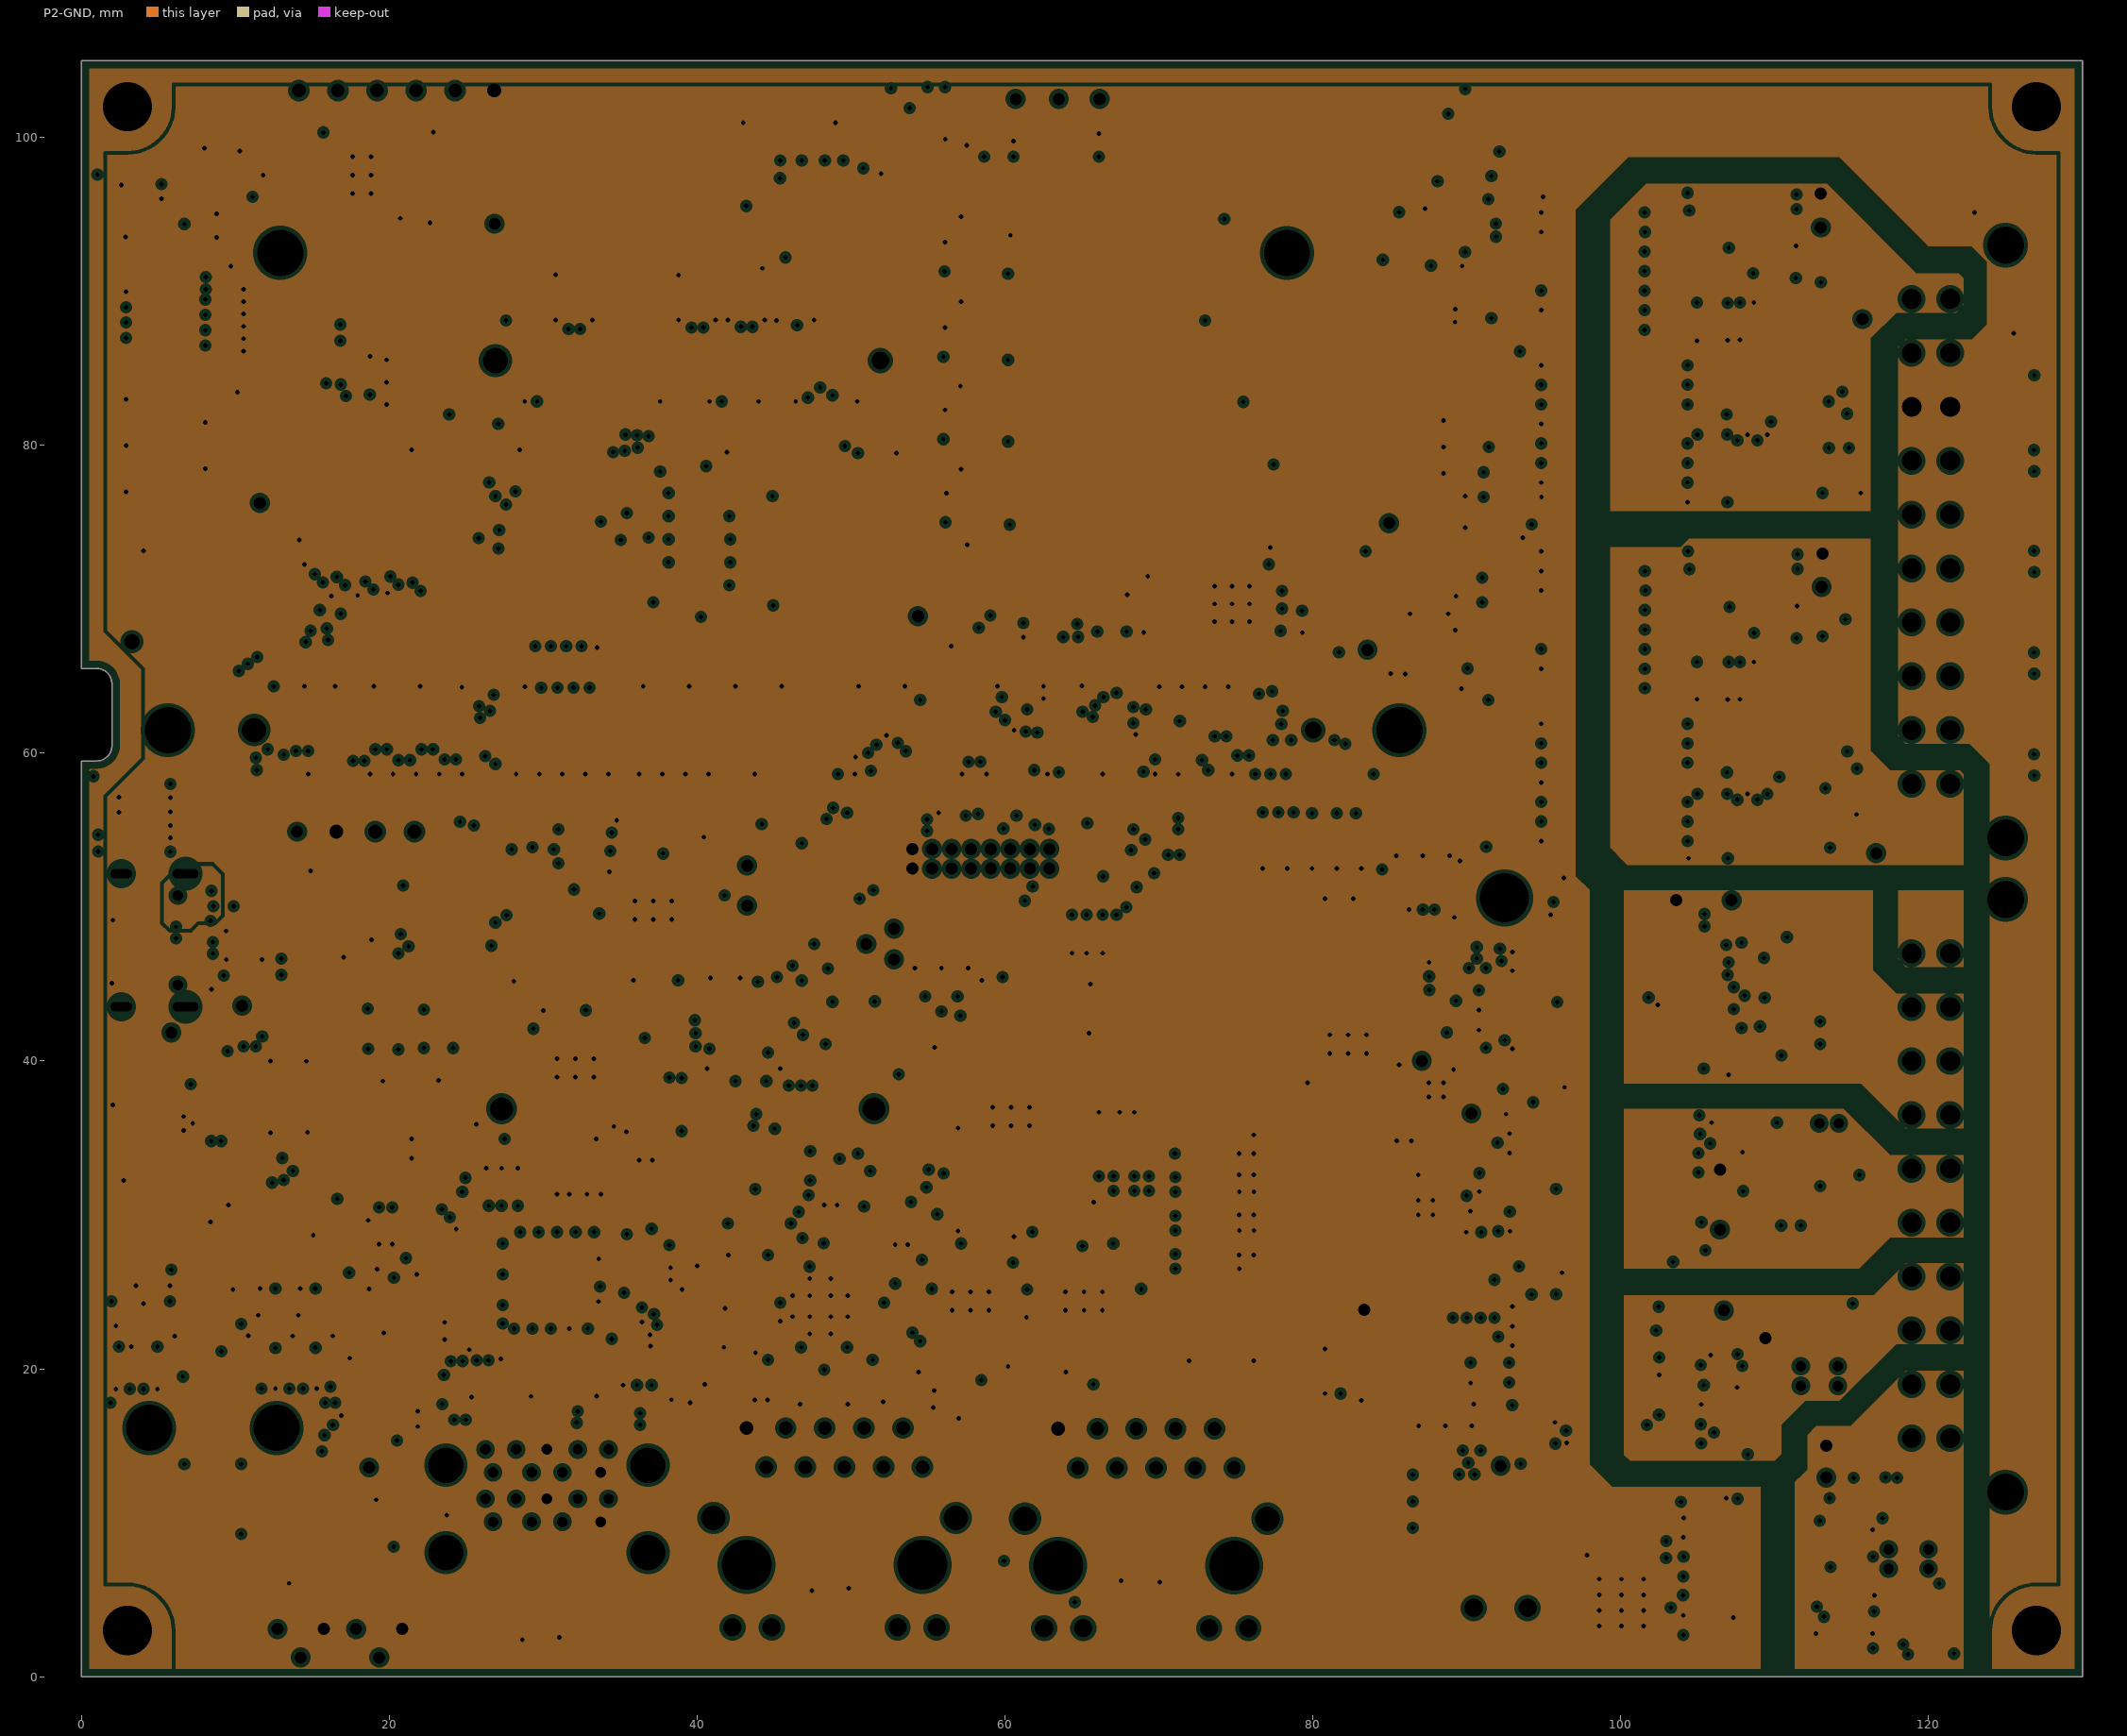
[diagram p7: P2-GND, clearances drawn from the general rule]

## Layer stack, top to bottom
Top Solder: solder mask 0.02, Solder Resist, Dk 3.5
Top Layer: signal copper 0.035
Dielectric1: prepreg 0.15, FR-4, Dk 4.2
P1-GND: plane copper 0.035, net (Multiple Nets)
Dielectric7: core 0.25, FR-4, Dk 4.2
L1-Signal: signal copper 0.035
Dielectric 1: prepreg 0.15, FR-4, Dk 4.2
L2-Signal: signal copper 0.035
Dielectric3: core 0.25, FR-4, Dk 4.2
L3-Signal: signal copper 0.035
Dielectric 2: prepreg 0.15, FR-4, Dk 4.2
L4-Signal: signal copper 0.035
Dielectric2: core 0.25, FR-4, Dk 4.2
P2-GND: plane copper 0.035, net (Multiple Nets)
Dielectric8: prepreg 0.15, FR-4, Dk 4.2
Bottom Layer: signal copper 0.035
Bottom Solder: solder mask 0.02, Solder Resist, Dk 3.5

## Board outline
0,0 0,59.5 1,59.5 ccw(c1,60.5) 2,60.5 2,64.5 ccw(c1,64.5) 1,65.5 0,65.5 0,105 130,105 130,0

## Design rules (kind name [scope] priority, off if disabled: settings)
AcuteAngle [All] p1: minimum=6.00000000000000E+0001 checktracksonly=FALSE
AssemblyTestPointUsage [All] p1: valid=2
BoardOutlineClearance [All] p1: gap=0.25 ignorepadtopadclearanceinfootprint=FALSE except(0: Arc-SplitContinuation Track-SplitContinuation SMDPad-SplitContinuation THPad-SplitContinuation Via-SplitContinuation Fill-SplitContinuation Poly-SplitContinuation Region-SplitContinuation Text-SplitContinuation)
Clearance Clearance_MHoles_SHLD [(IsPad AND OnLayer('Multi-Layer') AND InNet('SHLD')) vs (IsTrack AND OnLayer('Keep-Out Layer'))] p1: gap=0 ignorepadtopadclearanceinfootprint=TRUE // SHLD
Clearance Clearance_MHoles_STANDOFFs [(IsArc AND (HasFootprint('WURTH_9774025243R') OR HasFootprint('MTG_POST WURTH 774070243'))) vs InComponent('M1')] p2: gap=0 ignorepadtopadclearanceinfootprint=TRUE
Clearance Clearance_V+ [(InNet('V+') OR InNet('V-') OR InNet('V1') OR InNet('Vin')) vs NOT (InComponent('PTC7') OR InComponent('PTC8'))] p3: gap=0.5 ignorepadtopadclearanceinfootprint=TRUE
Clearance Clearance_Poly-SHLD_GND [(InNamedPolygon('SHLD_L01_P001') OR InNamedPolygon('SHLD_L08_P000')) vs InNet('GND')] p4: gap=0.4 ignorepadtopadclearanceinfootprint=TRUE
Clearance Clearance_Poly-VIN [(InNamedPolygon('VIN_L06'))] p5: gap=0.4 ignorepadtopadclearanceinfootprint=FALSE
Clearance Clearance_Poly-ETH1 [InNet('NetC2_2') vs InDifferentialPairClass('ETH1')] p6: gap=0.5 ignorepadtopadclearanceinfootprint=TRUE
Clearance Clearance_Poly-GND_ETH [InPolygon vs InDifferentialPairClass('ETH1')   or InDifferentialPairClass('ETH2')] p7: gap=0.5 ignorepadtopadclearanceinfootprint=TRUE
Clearance Clearance_Poly-GND_USB [InPolygon vs InDifferentialPairClass('USB')] p8: gap=0.254 ignorepadtopadclearanceinfootprint=TRUE
Clearance Clearance_Poly-GND_PCIe [InPolygon vs InDifferentialPairClass('PCIE')] p9: gap=0.254 ignorepadtopadclearanceinfootprint=TRUE
Clearance Clearance_Poly-GND_DSI [InPolygon vs InDifferentialPairClass('DSI')  or InDifferentialPairClass('DSI_1_CON')] p10: gap=0.254 ignorepadtopadclearanceinfootprint=TRUE
Clearance Clearance_Poly-GND_50R [InPolygon vs InNetClass('SD1') or InNetClass('SPI') or InNetClass('MDIO') or InNetClass('RGMII_RX') or InNetClass('RGMII_TX')] p11: gap=0.3 ignorepadtopadclearanceinfootprint=TRUE
Clearance [All] p12: gap=0.15 ignorepadtopadclearanceinfootprint=TRUE except(0.2: Via-Hole Text-Hole)
ComponentClearance [All] p1 off: gap=0 collisioncheckmode=3 verticalgap=0.15 showdistances=FALSE
DiffPairsRouting DiffPairsRouting_USB [InDifferentialPairClass('USB') or InDifferentialPairClass('USB1') or InDifferentialPairClass('USB2') or InDifferentialPairClass('USB3') or InDifferentialPairClass('USB4') or InDifferentialPairClass('USB') or InDifferentialPairClass('USB_3') or InDifferentialPairClass('USB_4') or InDifferentialPairClass('USB_2_SS')] p1: maxlimit=0.25 minlimit=0.127 mostfreqgap=0.15 toplayer_mingap=0.15 toplayer_maxgap=0.15 toplayer_minwidth=0.2 toplayer_maxwidth=0.2 toplayer_prefwidth=0.2 midlayer1_mingap=0.25 midlayer1_prefgap=0.25 midlayer1_minwidth=0.15 midlayer1_maxwidth=0.15 midlayer1_prefwidth=0.15 midlayer2_mingap=0.25 midlayer2_prefgap=0.25 midlayer2_minwidth=0.15 midlayer2_maxwidth=0.15 midlayer2_prefwidth=0.15 bottomlayer_mingap=0.15 bottomlayer_maxgap=0.15 bottomlayer_minwidth=0.2 bottomlayer_maxwidth=0.2 bottomlayer_prefwidth=0.2 impedanceprofiledriven=TRUE impedanceprofileid={0793B374-4453-4189-AA1D-FB60E5018E70} impedanceprofilevalue=90.000000 maxuncoupledlength=12.7
DiffPairsRouting DiffPairsRouting_ETH [InDifferentialPairClass('ETH1') or InDifferentialPairClass('LAN')] p2: maxlimit=0.5 minlimit=0.127 mostfreqgap=0.5 toplayer_mingap=0.15 toplayer_maxgap=0.15 toplayer_prefgap=0.15 toplayer_minwidth=0.18 toplayer_maxwidth=0.18 toplayer_prefwidth=0.18 midlayer1_mingap=0.35 midlayer1_maxgap=0.35 midlayer1_prefgap=0.35 midlayer1_minwidth=0.15 midlayer1_maxwidth=0.15 midlayer1_prefwidth=0.15 midlayer2_mingap=0.35 midlayer2_maxgap=0.35 midlayer2_prefgap=0.35 midlayer2_minwidth=0.15 midlayer2_maxwidth=0.15 midlayer2_prefwidth=0.15 bottomlayer_mingap=0.15 bottomlayer_maxgap=0.15 bottomlayer_prefgap=0.15 bottomlayer_minwidth=0.18 bottomlayer_maxwidth=0.18 bottomlayer_prefwidth=0.18 impedanceprofiledriven=TRUE impedanceprofileid={939C7A52-FDB8-4D9C-82B3-F762C21D684B} impedanceprofilevalue=95.000000 maxuncoupledlength=12.7
DiffPairsRouting DiffPairsRouting_DSI [InDifferentialPairClass('DSI') or InDifferentialPairClass('DSI_1_CON')] p3: maxlimit=1 minlimit=0.127 mostfreqgap=0.4 toplayer_mingap=0.15 toplayer_maxgap=0.15 toplayer_prefgap=0.15 toplayer_minwidth=0.2 toplayer_maxwidth=0.2 toplayer_prefwidth=0.2 midlayer1_mingap=0.25 midlayer1_maxgap=0.25 midlayer1_prefgap=0.25 midlayer1_minwidth=0.15 midlayer1_maxwidth=0.15 midlayer1_prefwidth=0.15 midlayer2_mingap=0.25 midlayer2_maxgap=0.25 midlayer2_prefgap=0.25 midlayer2_minwidth=0.15 midlayer2_maxwidth=0.15 midlayer2_prefwidth=0.15 bottomlayer_mingap=0.15 bottomlayer_maxgap=0.15 bottomlayer_prefgap=0.15 bottomlayer_minwidth=0.2 bottomlayer_maxwidth=0.2 bottomlayer_prefwidth=0.2 impedanceprofiledriven=TRUE impedanceprofileid={0793B374-4453-4189-AA1D-FB60E5018E70} impedanceprofilevalue=90.000000 maxuncoupledlength=30
DiffPairsRouting DiffPairsRouting_PCIe [InDifferentialPairClass('PCIE')] p4: maxlimit=1 minlimit=0.127 mostfreqgap=0.4 toplayer_mingap=0.15 toplayer_maxgap=0.15 toplayer_prefgap=0.15 toplayer_minwidth=0.2 toplayer_maxwidth=0.2 toplayer_prefwidth=0.2 midlayer1_mingap=0.25 midlayer1_maxgap=0.25 midlayer1_prefgap=0.25 midlayer1_minwidth=0.15 midlayer1_maxwidth=0.15 midlayer1_prefwidth=0.15 midlayer2_mingap=0.25 midlayer2_maxgap=0.25 midlayer2_prefgap=0.25 midlayer2_minwidth=0.15 midlayer2_maxwidth=0.15 midlayer2_prefwidth=0.15 bottomlayer_mingap=0.15 bottomlayer_maxgap=0.15 bottomlayer_prefgap=0.15 bottomlayer_minwidth=0.2 bottomlayer_maxwidth=0.2 bottomlayer_prefwidth=0.2 impedanceprofiledriven=TRUE impedanceprofileid={0793B374-4453-4189-AA1D-FB60E5018E70} impedanceprofilevalue=90.000000 maxuncoupledlength=30
FabricationTestPointUsage TestPointUsage [All] p1: valid=2 allowmultiple=FALSE
FabricationTestpoint Testpoint [(IsPad And (OnTopLayer Or OnBottomLayer))] p1: side=3 testpointundercomponent=TRUE minsize=1.016 maxsize=2.54 preferedsize=1.524 minholesize=0 maxholesize=1.016 preferedholesize=0.813 testpointgrid=0.025 allowsidetop=TRUE allowsidebottom=TRUE usegrid=TRUE gridtolerance=0
Height [All] p1: minheight=0 maxheight=40 prefheight=12.7
HoleSize [All] p1: absolutevalues=TRUE maxlimit=4.8 minlimit=0.3 maxpercent=80.000 minpercent=20.000
HoleToHoleClearance HoleToHoleClearance_U32 [HasFootprint('SOP-9 TP_ALT') vs HasFootprint('SOP-9 TP_ALT')] p1: gap=0 allowstackedmicrovias=TRUE
HoleToHoleClearance HoleToHoleClearance_LTE_conn [HasFootprint('17758622_FULL_SIZE') vs HasFootprint('MINI_PCIE_52PIN_CARD_LATCH_ALT')] p2: gap=0 allowstackedmicrovias=TRUE
HoleToHoleClearance HoleToHoleClearance_Mnt_Holes [(HasFootprint('WURTH_9774025243R') OR HasFootprint('MTG_POST WURTH 774070243')) vs HasFootprint('CON-TE-2309409-2_TORADEX_VERDIN_MTG_rev2')] p3: gap=0 allowstackedmicrovias=TRUE
HoleToHoleClearance [All] p4: gap=0.254 allowstackedmicrovias=TRUE
Length Length_MDIO [InNetClass('MDIO')] p1: maxlimit=55 minlimit=0
Length Length_RGMII [InNetClass('RGMII_RX') OR InNetClass('RGMII_TX')] p2: maxlimit=50 minlimit=0
MatchedLengths MatchedLengths_USBH_1_Pairs [InxSignalClass('USB_CHJ16_1')] p1: tolerance=0.127 checknetsindiffpair=TRUE checkdiffpairvsdiffpair=FALSE checkxsignals=FALSE checkothers=FALSE usedelayunits=TRUE delaytolerance=1.000000
MatchedLengths MatchedLengths_USBH_1_Group [InxSignalClass('USB_CHJ16_1')] p2: tolerance=0.127 checknetsindiffpair=FALSE checkdiffpairvsdiffpair=TRUE checkxsignals=TRUE checkothers=TRUE usedelayunits=TRUE delaytolerance=1.600000 targetsourcename=DS2_TX_N-DS2_N_PP1
MatchedLengths MatchedLengths_USBH_2_Pair [InxSignalClass('USB_CHJ16_2')] p3: tolerance=0.127 checknetsindiffpair=TRUE checkdiffpairvsdiffpair=FALSE checkxsignals=FALSE checkothers=FALSE usedelayunits=TRUE delaytolerance=1.000000
MatchedLengths MatchedLengths_USBH_1_Group_2 [InxSignalClass('USB_CHJ16_2')] p4: tolerance=0.127 checknetsindiffpair=FALSE checkdiffpairvsdiffpair=TRUE checkxsignals=TRUE checkothers=TRUE usedelayunits=TRUE delaytolerance=1.600000 targetsourcename=DS3_TX_N-DS3_N_PP1
MatchedLengths MatchedLengths_USB_Pair [InDifferentialPairClass('USB')] p5: tolerance=0.127 checknetsindiffpair=TRUE checkdiffpairvsdiffpair=FALSE checkxsignals=FALSE checkothers=FALSE usedelayunits=TRUE delaytolerance=7.500000
MatchedLengths MatchedLengths_DSI_1_InPair [InxSignalClass('DSI')] p6: tolerance=3 checknetsindiffpair=TRUE checkdiffpairvsdiffpair=FALSE checkxsignals=FALSE checkothers=FALSE usedelayunits=TRUE delaytolerance=1.000000
MatchedLengths MatchedLengths_DSI_1_Group [InxSignalClass('DSI')] p7: tolerance=3 checknetsindiffpair=FALSE checkdiffpairvsdiffpair=TRUE checkxsignals=TRUE checkothers=TRUE usedelayunits=TRUE delaytolerance=10.000000
MatchedLengths MatchedLengths_PCIe_InPair [InDifferentialPairClass('PCIE')] p8: tolerance=3 checknetsindiffpair=TRUE checkdiffpairvsdiffpair=FALSE checkxsignals=FALSE checkothers=FALSE usedelayunits=TRUE delaytolerance=1.000000
MatchedLengths MatchedLengths_ETH1 [InDifferentialPairClass('ETH1')] p9: tolerance=3 checknetsindiffpair=TRUE checkdiffpairvsdiffpair=FALSE checkxsignals=FALSE checkothers=FALSE usedelayunits=TRUE delaytolerance=1.600000
MatchedLengths MatchedLengths_ETH2 [InDifferentialPairClass('ETH2')] p10: tolerance=3 checknetsindiffpair=TRUE checkdiffpairvsdiffpair=FALSE checkxsignals=FALSE checkothers=FALSE usedelayunits=TRUE delaytolerance=1.600000
MatchedLengths MatchedLengths_USB [InDifferentialPairClass('USB')] p11: tolerance=3 checknetsindiffpair=TRUE checkdiffpairvsdiffpair=FALSE checkxsignals=FALSE checkothers=FALSE usedelayunits=TRUE delaytolerance=7.500000
MatchedLengths MatchedLengths_MDIO [InNetClass('MDIO')] p12: tolerance=0.508 checknetsindiffpair=FALSE checkdiffpairvsdiffpair=TRUE checkxsignals=TRUE checkothers=TRUE usedelayunits=TRUE delaytolerance=3.000000
MatchedLengths MatchedLengths_RGMI_TX [InNetClass('RGMII_TX')] p13: tolerance=3 checknetsindiffpair=FALSE checkdiffpairvsdiffpair=TRUE checkxsignals=TRUE checkothers=TRUE usedelayunits=TRUE delaytolerance=3.000000
MatchedLengths MatchedLengths_RGMI_RX [InNetClass('RGMII_RX')] p14: tolerance=3 checknetsindiffpair=FALSE checkdiffpairvsdiffpair=TRUE checkxsignals=TRUE checkothers=TRUE usedelayunits=TRUE delaytolerance=3.000000
MatchedLengths MatchedLengths_SD1 [InNetClass('SD1')] p15: tolerance=3 checknetsindiffpair=FALSE checkdiffpairvsdiffpair=TRUE checkxsignals=TRUE checkothers=TRUE usedelayunits=TRUE delaytolerance=20.000000
MinimumAnnularRing [InComponent('U26')] p1: minimumring=0
MinimumSolderMaskSliver MinimumSolderMaskSliver_STRING [InComponent('MECH1')] p1: minsoldermaskwidth=0 // Toradex Logo and P/N
MinimumSolderMaskSliver MinimumSolderMaskSliver_ALL [All] p2: minsoldermaskwidth=0.05
NetAntennae [All] p1: netantennaetolerance=1
PlaneClearance [All] p1: clearance=0.254
PlaneConnect [All] p1: pad.planeconnectstyle=Relief pad.reliefexpansion=0.25 pad.reliefentries=4 pad.reliefconductorwidth=0.25 pad.reliefairgap=0.2 via.planeconnectstyle=Direct via.reliefexpansion=0.25 via.reliefentries=4 via.reliefconductorwidth=0.25 via.reliefairgap=0.2
PolygonConnect PolygonConnect_TOP/BOT [OnLayer('Top Layer') or OnLayer('Bottom Layer')] p1: connectstyle=Direct reliefconductorwidth=0.254 reliefentries=4 polygonreliefangle="90 Angle" airgapwidth=0.254 // Direct connect for TOP/BOT polygons
PolygonConnect PolygonConnect_SHLD [InNet('SHLD')] p2: connectstyle=Direct reliefconductorwidth=0.254 reliefentries=4 polygonreliefangle="90 Angle" airgapwidth=0.254
PolygonConnect PolygonConnect_VIN [InNet('VIN')] p3: connectstyle=Direct reliefconductorwidth=0.254 reliefentries=4 polygonreliefangle="90 Angle" airgapwidth=0.254
PolygonConnect PolygonConnect_Via [Isvia] p4: connectstyle=Direct reliefconductorwidth=0.254 reliefentries=4 polygonreliefangle="90 Angle" airgapwidth=0.254
PolygonConnect [All] p5: thpad.connectstyle=Relief thpad.reliefconductorwidth=0.25 thpad.reliefentries=4 thpad.polygonreliefangle="90 Angle" thpad.airgapwidth=0.2 smdpad.connectstyle=Relief smdpad.reliefconductorwidth=0.25 smdpad.reliefentries=4 smdpad.polygonreliefangle="90 Angle" smdpad.airgapwidth=0.2 via.connectstyle=Direct via.reliefconductorwidth=0.25 via.reliefentries=4 via.polygonreliefangle="90 Angle" via.airgapwidth=0.2
RoutingVias RoutingVias_RGZ [InNamedUnion('U26')] p1: holewidth=0.3 width=0 viastyle="Through Hole" minholewidth=0.3 minwidth=0 maxholewidth=5 maxwidth=5
RoutingVias [All] p2: holewidth=0.3 width=0.6 viastyle="Through Hole" minholewidth=0.3 minwidth=0.6 maxholewidth=5 maxwidth=5
ShortCircuit ShortCircuit_JP1 [InNet('NetC186_1') vs InNet('GND_AIN1')] p1: allowed=TRUE
ShortCircuit ShortCircuit_JP2 [InNet('NetC188_1') vs InNet('GND_AIN2')] p2: allowed=TRUE
ShortCircuit ShortCircuit_LTE_LATCH [HasFootprint('17758622_FULL_SIZE') vs HasFootprint('MINI_PCIE_52PIN_CARD_LATCH_ALT')] p3: allowed=TRUE
ShortCircuit ShortCircuit_M1_Holes [InPadClass('M1')] p4: allowed=TRUE
ShortCircuit ShortCircuit_M1_Holes_1 [(IsArc AND HasFootprint('WURTH_9774025243R') OR HasFootprint('MTG_POST WURTH 774070243'))] p5: allowed=TRUE
ShortCircuit [All] p6: allowed=FALSE
SilkToSilkClearance [All] p1: silktosilkclearance=0
SilkToSolderMaskClearance SilkscreenOverComponentPads [IsPad] p1: minsilkscreentomaskgap=0.05 clearancetoexposedcopper=TRUE
SolderMaskExpansion [All] p1: expansion=0.074 istentingtop=FALSE
SupplyNets "Schematic Supply Nets_40" [InNet('AVDD12')] p1: voltage=0.000
SupplyNets "Schematic Supply Nets_39" [InNet('GND_CAN2')] p2: voltage=0.000
SupplyNets "Schematic Supply Nets_38" [InNet('MPCI1_3V3')] p3: voltage=0.000
SupplyNets "Schematic Supply Nets_37" [InNet('GND')] p4: voltage=0.000
SupplyNets "Schematic Supply Nets_36" [InNet('1V8_CAN')] p5: voltage=0.000
SupplyNets "Schematic Supply Nets_35" [InNet('GND_485')] p6: voltage=0.000
SupplyNets "Schematic Supply Nets_34" [InNet('1V0_ETH')] p7: voltage=0.000
SupplyNets "Schematic Supply Nets_33" [InNet('GND_232')] p8: voltage=0.000
SupplyNets "Schematic Supply Nets_32" [InNet('5V_AIN2')] p9: voltage=0.000
SupplyNets "Schematic Supply Nets_31" [InNet('3V3')] p10: voltage=0.000
SupplyNets "Schematic Supply Nets_30" [InNet('3V2_AIN1')] p11: voltage=0.000
SupplyNets "Schematic Supply Nets_29" [InNet('PWR1')] p12: voltage=0.000
SupplyNets "Schematic Supply Nets_28" [InNet('PWR_1V8')] p13: voltage=0.000
SupplyNets "Schematic Supply Nets_27" [InNet('1V8')] p14: voltage=0.000
SupplyNets "Schematic Supply Nets_26" [InNet('5V_CAN1')] p15: voltage=0.000
SupplyNets "Schematic Supply Nets_25" [InNet('PWR2')] p16: voltage=0.000
SupplyNets "Schematic Supply Nets_24" [InNet('VCC_232')] p17: voltage=0.000
SupplyNets "Schematic Supply Nets_23" [InNet('1V8_SW')] p18: voltage=0.000
SupplyNets "Schematic Supply Nets_22" [InNet('MPCI1_1V5')] p19: voltage=0.000
SupplyNets "Schematic Supply Nets_21" [InNet('AVDD33')] p20: voltage=0.000
SupplyNets "Schematic Supply Nets_20" [InNet('VIN')] p21: voltage=0.000
SupplyNets "Schematic Supply Nets_19" [InNet('SHLD')] p22: voltage=0.000
SupplyNets "Schematic Supply Nets_18" [InNet('3V2_AIN2')] p23: voltage=0.000
SupplyNets "Schematic Supply Nets_17" [InNet('5V_AIN1')] p24: voltage=0.000
SupplyNets "Schematic Supply Nets_16" [InNet('GND_AIN2')] p25: voltage=0.000
SupplyNets "Schematic Supply Nets_15" [InNet('V+')] p26: voltage=0.000
SupplyNets "Schematic Supply Nets_14" [InNet('5V')] p27: voltage=0.000
SupplyNets "Schematic Supply Nets_13" [InNet('5V_485')] p28: voltage=0.000
SupplyNets "Schematic Supply Nets_12" [InNet('VT')] p29: voltage=0.000
SupplyNets "Schematic Supply Nets_11" [InNet('V-')] p30: voltage=0.000
SupplyNets "Schematic Supply Nets_10" [InNet('5V_CAN')] p31: voltage=0.000
SupplyNets "Schematic Supply Nets_9" [InNet('GND_AIN1')] p32: voltage=0.000
SupplyNets "Schematic Supply Nets_8" [InNet('VBAT')] p33: voltage=0.000
SupplyNets "Schematic Supply Nets_7" [InNet('DVDD12')] p34: voltage=0.000
SupplyNets "Schematic Supply Nets_6" [InNet('5V_CAN2')] p35: voltage=0.000
SupplyNets "Schematic Supply Nets_5" [InNet('+V5_SW')] p36: voltage=0.000
SupplyNets "Schematic Supply Nets_4" [InNet('V1')] p37: voltage=0.000
SupplyNets "Schematic Supply Nets_3" [InNet('GND_CAN1')] p38: voltage=0.000
SupplyNets "Schematic Supply Nets_2" [InNet('1V8C')] p39: voltage=0.000
SupplyNets "Schematic Supply Nets_1" [InNet('2V5')] p40: voltage=0.000
SupplyNets "Schematic Supply Nets" [InNet('TOP_5V')] p41: voltage=0.000
UnRoutedNet [All] p1: checkbadconnections=TRUE
ViasUnderSMD [All] p1: allowed=TRUE
Width Width_S50 [InNetClass('SD1') or InNetClass('SPI') OR InNetClass('MDIO') OR InNetClass('RGMII_RX') OR InNetClass('RGMII_TX')] p1: maxlimit=0.25 minlimit=0.127 preferedwidth=0.15 toplayer_minwidth=0.25 toplayer_prefwidth=0.25 midlayer1_minwidth=0.15 midlayer1_maxwidth=0.15 midlayer2_minwidth=0.15 midlayer2_maxwidth=0.15 bottomlayer_minwidth=0.25 bottomlayer_prefwidth=0.25 impedanceprofiledriven=TRUE impedanceprofileid={3BBE8C65-274D-4309-B5D1-2B8FC1ED8F61} impedanceprofilevalue=50.000000 minimp=50.000000 maximp=50.000000 favimp=50.000000 checkconnectedcopper=TRUE
Width [All] p2: maxlimit=2 minlimit=0.1 preferedwidth=0.15 checkconnectedcopper=TRUE
14 further rules are at their usual default settings.

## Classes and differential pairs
differential pair class USB2_SS: USB_2_SSRX USB_2_SSTX
net class RGMII_TX: RGMII.RGMII_TX_CTRL RGMII.RGMII_TXC RGMII.RGMII_TXD_0 RGMII.RGMII_TXD_1 RGMII.RGMII_TXD_2 RGMII.RGMII_TXD_3
net class RGMII_RX: RGMII.RGMII_RX_CTRL RGMII.RGMII_RXC RGMII.RGMII_RXD_0 RGMII.RGMII_RXD_1 RGMII.RGMII_RXD_2 RGMII.RGMII_RXD_3
component class U_900_LTE: C167 C168 C169 C170 C171 C172 C173 C174 C175 C176 C177 C178 C179 C180 D18 D19 D20 D21 D22 J8 J9 J11 L27 L28 L29 L30 R132 R133 R134 R135 R136 R137 R138 R139 R141 R142 R143 R144 R145 R146 R148 R149 R150 R151 R152 R153 R229 R230 R231 R232 U31 U32 U33 X55
component class U_850_850_DIGIN: D27 D28 D29 D30 L32 R193 R194 R195 R196 R197 R198 U60 U61 U62 U63
component class U_840_ADC: C183 C184 C185 C186 C187 C188 C189 C190 C191 C192 C193 C194 C195 C196 C197 C198 C199 C200 C201 C202 C203 C204 C205 C206 C207 C208 C209 C210 C211 C212 C213 C214 C215 C216 D24 D25 JP1 JP2 PTC5 PTC6 Q9 Q10 R84 R158 R159 R160 R161 R162 R163 R164 R165 R166 R167 R168 R169 R170 R171 R172 R173 R174 R175 R176 R177 R178 R179 R180 R181 R182 R183 R184 R251 R252 R253 R254 R255 R256 R257 R258 R259 R260 R261 R262 R273 R274 R275 R276 RA6 RA7 U37 U38 U39 U40 U41 U42 U43 U44 U45 U46 U47 U48 X58 X59 X60 X61 X62 X63 X64 X65
component class U_820_MicroSD: C181 C182 J12 L31 R154 R155 R156 R157 U34 U35 U36 X56 X57
component class U_815_IO_Connectors: D23 D26 J5 J6 PTC7 PTC8
component class U_810_AUX_Connectors: C239 C240 C241 C242 C243 C244 C245 C246 C247 C248 C249 C250 C251 C252 J13 J15 L33 L34 L35 L36 L37 L38 L39 R199 R200 R201 R202 R203 R204 R205 R206 R207 R208 R209 R210 U64 U65 U66 U67 X79 X80 X81
component class U_800_Peripherals: C9 C10 C11 C12 C13 C14 C15 C16 J2 L4 R8 R9 R10 R11 R140 R147 R218 R219 S1 S2 U3 U4 U5 U6 U7 X3 X4 X5 X6 X7 X8 X9 X10 X11 XS1
component class U_700_Relays: D10 D11 D12 D13 D14 D15 D16 D17 PR1 PR2 PR3 PR4 PTC1 PTC2 PTC3 PTC4 Q5 Q6 Q7 Q8 R98 R99 R100 R101 R102 R103 R104 R105 R106 R107 R108 R109 R110 R111 R112 R113
component class U_620_Ethernet2: C133 C134 C135 C136 C137 C138 C139 C140 C141 C142 C143 C144 C145 C146 C147 C148 C149 C150 C151 C152 C153 C154 C155 C156 C157 C158 C159 C160 C161 C162 C163 C164 C165 C166 J7 L26 Q14 R114 R115 R116 R117 R118 R119 R120 R121 R122 R123 R124 R125 R126 R127 R128 R129 R130 R131 R220 R221 R265 R266 R267 R268 U26 U27 U28 U29 U30 X51 X52 X53 Y2
component class U_600_Ethernet: C2 J10 R1 R2 R3 U1 U2
component class U_510_USB_Type_A_Conn: C253 C254 C255 C256 C257 C258 C259 C260 D31 J16 L40 R213 R214 R216 R223 U68 U69 U70 U71 X83
component class U_500_USB_HUB: C17 C18 C19 C20 C21 C22 C23 C24 C25 C26 C27 C28 C29 C30 C31 C32 C33 C34 C35 C36 C37 C38 C39 C40 C41 C42 C43 C44 C45 C46 C47 C48 C49 C50 C51 C52 C53 C54 C55 C56 C57 C58 C59 C60 C61 C62 C63 C64 C65 C66 L5 L6 L7 Q11 R12 R13 R14 R15 R16 R17 R18 R19 R20 R21 R22 R23 R24 R25 R26 R211 R212 R217 U8 U9 X13 X14 Y1
component class U_400_USB1_OTG: C104 C106 C107 C108 C109 D32 J4 L15 L16 L17 L18 R58 R59 R60 R61 R62 R63 R64 R65 R66 U13 U14 U15 X19 X20 X21 X22 X23 X24 X25
component class U_330_RS-485: C217 C218 C219 C220 C221 C222 C223 C224 C225 J14 R185 R186 R187 R188 R189 R190 R241 R242 R243 R244 U49 U50 U51 U52 U59 X69 X70
component class U_320_RS-232: C226 C227 C228 C229 C230 C231 C232 C233 C234 C235 C236 C237 C238 R191 R192 R245 R246 R247 R248 R249 R250 U53 U54 U55 U56 U57 U58 X77 X78
component class U_300_CAN_Transceivers: C115 C116 C117 C118 C119 C120 C121 C122 C123 C124 C125 C126 C127 C128 C129 C130 C131 C132 J18 J19 J20 J21 L24 L25 R86 R87 R88 R89 R90 R91 R92 R93 R94 R95 R96 R97 R225 R226 R227 R228 R233 R234 R235 R236 R237 R238 R239 R240 U18 U19 U20 U21 U22 U23 U24 U25 X30 X31 X32 X33
component class U_240_Translators: C111 C114 R215 R222 R272 RA1 RA2 U16
component class U_220_Verdin_Full: C3 C4 C5 C6 C7 C8 J1 J17 L2 L3 M1 ME1 ME2 ME3 ME4 Q15 R4 R5 R6 R7 R85 R224 R264 R269 R270 R271 X2
component class U_150_Status_LEDs: D5 D7 D8 D9 LP1 Q1 Q2 Q3 Q4 Q13 R47 R67 R68 R69 R70 R71 R72 R73 R74 R75 R76 R77 R78 R79 R80 R81 R82 R83 R263
component class U_100_Power: C67 C68 C69 C70 C71 C72 C73 C74 C75 C76 C77 C78 C79 C80 C81 C82 C83 C84 C85 C86 C87 C88 C89 C90 C91 C92 C93 C94 C95 C96 C97 C98 C99 C100 C101 C102 C103 D1 D2 D3 D4 D6 F1 J3 L8 L9 L10 L11 L12 L13 L14 R27 R28 R29 R30 R31 R32 R33 R34 R35 R36 R37 R38 R39 R40 R41 R42 R43 R44 R45 R46 R48 R49 R50 R51 R52 R53 R54 R55 R56 R57 U10 U11 U12 X1 X15 X16 X17 X18
component class 000_Main: FID1 FID2 FID3 FID4 FID5 FID6 H1 H2 H3 H4 H5 LBL1 LBL2 MECH1
net class MDIO: RGMII.RGMII_MDC RGMII.RGMII_MDIO
pad class M1: M1-0 M1-1
differential pair class USBH1: USBHUB1.USBH1
net class SPI: GPIO1 SPI_CLK SPI_MISO SPI_MOSI
differential pair class DSI_1_CON: DSI_1_CLK_CON DSI_1_D0_CON DSI_1_D1_CON DSI_1_D2_CON DSI_1_D3_CON
differential pair class USB: DS2 DS2_RX DS2_TX DS3 DS3_RX DS3_TX USB1 USB2 USB_1 USB_2_SSRX USB_2_SSTX USBH2 USBH3 USBHUB1.USBH1
differential pair class CAN: CAN1 CAN2
differential pair class USBH3: DS3 DS3_RX DS3_TX USBH3
differential pair class USBH2: DS2 DS2_RX DS2_TX USBH2
differential pair class ETH2: ETH2_D0 ETH2_D1 ETH2_D2 ETH2_D3
differential pair class DSI: DSI_1_CLK DSI_1_CLK_CON DSI_1_D0 DSI_1_D0_CON DSI_1_D1 DSI_1_D1_CON DSI_1_D2 DSI_1_D2_CON DSI_1_D3 DSI_1_D3_CON
differential pair class USB2: USB2
differential pair class USB1: USB1
differential pair class RS485: RS485
differential pair class PCIE: PCIE_CLK PCIE_RX PCIE_TX
differential pair class ETH1: ETH1_D0 ETH1_D1 ETH1_D2 ETH1_D3
net class SD1: SD1_CLK SD1_CMD SD1_D0 SD1_D1 SD1_D2 SD1_D3
pad class S1: U26-49
differential pair USB_2_SSTX: +USB_2_SSTX_P -USB_2_SSTX_N
differential pair USB_2_SSRX: +USB_2_SSRX_P -USB_2_SSRX_N
differential pair CAN2: +CAN2_H -CAN2_L
differential pair CAN1: +CAN1_H -CAN1_L
differential pair USBHUB1.USBH1: +USBHUB1.USBH1_P -USBHUB1.USBH1_N
differential pair USBH3: +USBH3_P -USBH3_N
differential pair USBH2: +USBH2_P -USBH2_N
differential pair DS3: +DS3_P -DS3_N
differential pair DS3_TX: +DS3_TX_P -DS3_TX_N
differential pair DS3_RX: +DS3_RX_P -DS3_RX_N
differential pair DS2: +DS2_P -DS2_N
differential pair DS2_TX: +DS2_TX_P -DS2_TX_N
differential pair DS2_RX: +DS2_RX_P -DS2_RX_N
differential pair ETH2_D3: +ETH2_D3_P -ETH2_D3_N
differential pair ETH2_D2: +ETH2_D2_P -ETH2_D2_N
differential pair ETH2_D1: +ETH2_D1_P -ETH2_D1_N
differential pair ETH2_D0: +ETH2_D0_P -ETH2_D0_N
differential pair DSI_1_D3_CON: +DSI_1_D3_CON_P -DSI_1_D3_CON_N
differential pair DSI_1_D2_CON: +DSI_1_D2_CON_P -DSI_1_D2_CON_N
differential pair DSI_1_D1_CON: +DSI_1_D1_CON_P -DSI_1_D1_CON_N
differential pair DSI_1_D0_CON: +DSI_1_D0_CON_P -DSI_1_D0_CON_N
differential pair DSI_1_CLK_CON: +DSI_1_CLK_CON_P -DSI_1_CLK_CON_N
differential pair DSI_1_D3: +DSI_1_D3_P -DSI_1_D3_N
differential pair DSI_1_D2: +DSI_1_D2_P -DSI_1_D2_N
differential pair DSI_1_D1: +DSI_1_D1_P -DSI_1_D1_N
differential pair DSI_1_D0: +DSI_1_D0_P -DSI_1_D0_N
differential pair DSI_1_CLK: +DSI_1_CLK_P -DSI_1_CLK_N
differential pair USB_1: +USB_1_P -USB_1_N
differential pair USB2: +USB2_P -USB2_N
differential pair USB1: +USB1_P -USB1_N
differential pair RS485: +RS485_P -RS485_N
differential pair PCIE_TX: +PCIE_TX_P -PCIE_TX_N
differential pair PCIE_RX: +PCIE_RX_P -PCIE_RX_N
differential pair PCIE_CLK: +PCIE_CLK_P -PCIE_CLK_N
differential pair ETH1_D3: +ETH1_D3_P -ETH1_D3_N
differential pair ETH1_D2: +ETH1_D2_P -ETH1_D2_N
differential pair ETH1_D1: +ETH1_D1_P -ETH1_D1_N
differential pair ETH1_D0: +ETH1_D0_P -ETH1_D0_N

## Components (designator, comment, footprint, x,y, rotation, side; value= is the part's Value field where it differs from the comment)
C2 "0567-Cap-1206-1nF/2KV" C/1206 67.55,8.9 r90 bottom value=1nF/2KV
C3 "0753-Cap 3P-1206-1uF/100V/6A" C/1206_3P 87.15,53.35 r90 top value=1uF/100V/6A
C4 "22uF/6.3V" C0402_CAPC1005L 79.95,54.3 r90 top
C5 "22uF/6.3V" C0402_CAPC1005L 78.35,54.3 r90 top
C6 "22uF/6.3V" C0402_CAPC1005L 76.75,54.3 r90 top
C7 "22uF/6.3V" C0402_CAPC1005L 83.15,54.3 r90 top
C8 "22uF/6.3V" C0402_CAPC1005L 81.55,54.3 r90 top
C9 "100nF" C0402_CAPC1005L 70.5,71.5 r0 bottom
C10 "100nF" C0402_CAPC1005L 78.6,68.3 r90 bottom
C11 "100nF" C0402_CAPC1005L 70.25,67.85 r0 bottom
C12 "22uF/6.3V" C0402_CAPC1005L 69.9,70.3 r0 bottom
C13 "100nF" C0402_CAPC1005L 76,73.35 r180 bottom
C14 "100nF" C0402_CAPC1005L 61.25,99.25 r270 top
C15 "100nF" C0402_CAPC1005L 62.486,67.546 r0 bottom
C16 "100nF" C0402_CAPC1005L 2,58.5 r180 top
C17 "22uF/6.3V" C0402_CAPC1005L 30.511,21.35 r90 top
C18 "10nF" C0402_CAPC1005L 34.977,26.575 r180 top
C19 "1006-Cap-0402-1uF/6V3" C0402_CAPC1005L 28.106,21.374 r90 top value=1uF/6.3V
C20 "0318-Cap-0402-1nF/50V" C0402_CAPC1005L 34.977,25.775 r0 top value=1nF
C21 "22uF/6.3V" C0402_CAPC1005L 19.731,27.181 r0 top
C22 "0319-Cap-0402-12pF/50V" C0402_CAPC1005L 22.3,25.45 r0 bottom value=12pF
C23 "0319-Cap-0402-12pF/50V" C0402_CAPC1005L 22.3,21.9 r180 bottom value=12pF
C24 "10nF" C0402_CAPC1005L 32.95,27.6 r90 top
C25 "100nF" C0402_CAPC1005L 28.1,23.85 r270 top
C26 "1006-Cap-0402-1uF/6V3" C0402_CAPC1005L 25.9,25.9 r0 top value=1uF/6.3V
C27 "0318-Cap-0402-1nF/50V" C0402_CAPC1005L 31.35,27.6 r270 top value=1nF
C28 "100nF" C0402_CAPC1005L 35.2,20.2 r90 bottom
C29 "10nF" C0402_CAPC1005L 28.9,23.85 r270 top
C30 "100nF" C0402_CAPC1005L 25.9,28.3 r0 top
C31 "10nF" C0402_CAPC1005L 29.7,27.6 r90 top
C32 "100nF" C0402_CAPC1005L 31.3,23.85 r270 top
C33 "10nF" C0402_CAPC1005L 25.9,27.5 r0 top
C34 "0318-Cap-0402-1nF/50V" C0402_CAPC1005L 30.5,27.6 r270 top value=1nF
C35 "10nF" C0402_CAPC1005L 30.5,23.85 r270 top
C36 "100nF" C0402_CAPC1005L 25.9,24.3 r0 top
C37 "10nF" C0402_CAPC1005L 28.9,27.6 r90 top
C38 "100nF" C0402_CAPC1005L 33,23.85 r270 top
C39 "22uF/6.3V" C0402_CAPC1005L 26.15,35.166 r0 bottom
C40 "10nF" C0402_CAPC1005L 25.9,23.5 r0 top
C41 "0318-Cap-0402-1nF/50V" C0402_CAPC1005L 32.15,27.6 r270 top value=1nF
C42 "10nF" C0402_CAPC1005L 32.2,23.85 r270 top
C43 "1006-Cap-0402-1uF/6V3" C0402_CAPC1005L 24.9,22.55 r0 bottom value=1uF/6.3V
C44 "100nF" C0402_CAPC1005L 25.9,29.1 r0 top
C45 "10nF" C0402_CAPC1005L 28.35,31.85 r270 top
C46 "10nF" C0402_CAPC1005L 25.9,22.7 r0 top
C47 "10nF" C0402_CAPC1005L 25.9,29.9 r0 top
C48 "0318-Cap-0402-1nF/50V" C0402_CAPC1005L 27.3,31.85 r90 top value=1nF
C49 "0318-Cap-0402-1nF/50V" C0402_CAPC1005L 25.9,21.9 r180 top value=1nF
C50 "100nF" C0402_CAPC1005L 25.9,25.1 r0 top
C51 "10nF" C0402_CAPC1005L 29.311,21.35 r90 top
C52 "10nF" C0402_CAPC1005L 33.75,30.15 r270 top
C53 "10nF" C0402_CAPC1005L 25.9,26.7 r0 top
C54 "0318-Cap-0402-1nF/50V" C0402_CAPC1005L 29.7,23.85 r90 top value=1nF
C55 "0318-Cap-0402-1nF/50V" C0402_CAPC1005L 35.673,21.95 r0 top value=1nF
C56 "10nF" C0402_CAPC1005L 30.9,30.15 r270 top
C57 "10nF" C0402_CAPC1005L 32.85,30.15 r270 top
C58 "22uF/6.3V" C0402_CAPC1005L 30.95,44.15 r0 top
C59 "0318-Cap-0402-1nF/50V" C0402_CAPC1005L 35.673,21.15 r0 top value=1nF
C60 "0318-Cap-0402-1nF/50V" C0402_CAPC1005L 31.7,30.15 r90 top value=1nF
C61 "1314-Cap-0805-22uF/16V" C/0805 28.1,43.1 r270 top value=22uF/16V
C62 "100nF" C0402_CAPC1005L 35.673,23.525 r90 top
C63 "10nF" C0402_CAPC1005L 34.873,23.525 r90 top
C64 "100nF" C0402_CAPC1005L 37.1,32.35 r270 top
C65 "10nF" C0402_CAPC1005L 36.25,32.35 r270 top
C66 "22uF/6.3V" C0402_CAPC1005L 31.965,34.95 r180 top
C67 "0753-Cap 3P-1206-1uF/100V/6A" C/1206_3P 88.498,79.896 r180 top value=1uF/100V/6A
C68 "0753-Cap 3P-1206-1uF/100V/6A" C/1206_3P 55.875,46.05 r90 top value=1uF/100V/6A
C69 "0753-Cap 3P-1206-1uF/100V/6A" C/1206_3P 88.6,16.3 r90 top value=1uF/100V/6A
C70 "CC1206KKX7R0BB225" C/1206 78.75,27.4 r0 top value=2.2uF/100V
C71 "1314-Cap-0805-22uF/16V" C/0805 87.748,76.696 r180 top value=22uF/16V
C72 "CC1206KKX7R0BB225" C/1206 78.75,30 r0 top value=2.2uF/100V
C73 "10uF/50V" CAPC3225N 62.95,41.8 r180 top
C74 "1314-Cap-0805-22uF/16V" C/0805 87.752,74.654 r180 top value=22uF/16V
C75 "CC1206KKX7R0BB225" C/1206 78.75,32.6 r0 top value=2.2uF/100V
C76 "CC1206KKX7R0BB225" C/1206 78.75,35.2 r0 top value=2.2uF/100V
C77 "10uF/50V" CAPC3225N 62.95,45 r180 top
C78 "CC1206KKX7R0BB225" C/1206 84.25,30 r180 top value=2.2uF/100V
C79 "CC1206KKX7R0BB225" C/1206 84.25,32.6 r180 top value=2.2uF/100V
C80 "0753-Cap 3P-1206-1uF/100V/6A" C/1206_3P 86.5,11.4 r0 top value=1uF/100V/6A
C81 "1470-Cap-0603-3.6nF" C/0603 58.85,29.3 r180 top value=3.6nF
C82 "100nF" C0402_CAPC1005L 63.625,36.4 r270 top
C83 "1602-Cap-0402-100pF" C0402_CAPC1005L 88.523,66.95 r0 top value=100pF
C84 "0000-Cap-0603-DNP" C/0603 61.15,31.05 r90 top value=DNP
C85 "1875-Cap-0603-2.2nF/100V" C/0603 84.725,46.5 r270 top value=2.2nF/100V
C86 "22uF/6.3V" C0402_CAPC1005L 93.15,71.4 r180 top
C87 "0000-Cap-0603-DNP" C/0603 56.55,30.9 r90 top value=DNP
C88 "22uF/6.3V" C0402_CAPC1005L 93.15,69.8 r180 top
C89 "22uF/6.3V" C0402_CAPC1005L 93.25,76.65 r180 top
C90 "1602-Cap-0402-100pF" C0402_CAPC1005L 86.3,46.85 r90 top value=100pF
C91 "22uF/6.3V" C0402_CAPC1005L 93.25,78.25 r180 top
C92 "1314-Cap-0805-22uF/16V" C/0805 73.125,34 r180 top value=22uF/16V
C93 "1875-Cap-0603-2.2nF/100V" C/0603 88.825,47.4 r0 top value=2.2nF/100V
C94 "1314-Cap-0805-22uF/16V" C/0805 68.4,34.6 r270 top value=22uF/16V
C95 "1314-Cap-0805-22uF/16V" C/0805 66.1,34.6 r270 top value=22uF/16V
C96 "1314-Cap-0805-22uF/16V" C/0805 73.15,26.5 r180 top value=22uF/16V
C97 "100nF" C0402_CAPC1005L 83.15,16.75 r90 top
C98 "1314-Cap-0805-22uF/16V" C/0805 73.15,29 r180 top value=22uF/16V
C99 "1314-Cap-0805-22uF/16V" C/0805 73.15,31.5 r180 top value=22uF/16V
C100 "100nF" C0402_CAPC1005L 4.3,53.613 r0 top
C101 "100nF" C0402_CAPC1005L 7,55.3 r180 top
C102 "0567-Cap-1206-1nF/2KV" C/1206 8,101.9 r90 top value=1nF/2KV
C103 "100nF" C0402_CAPC1005L 7,57.1 r180 top
C104 "1314-Cap-0805-22uF/16V" C/0805 7.15,33.2 r270 bottom value=22uF/16V
C106 "100nF" C0402_CAPC1005L 17.05,48 r90 bottom
C107 "0455-Cap-1206-100uF/6.3V" C/1206 2.75,32.4 r90 bottom value=100uF/6.3V
C108 "100nF" C0402_CAPC1005L 5.35,35.5 r180 bottom
C109 "0567-Cap-1206-1nF/2KV" C/1206 2.85,46.75 r0 bottom value=1nF/2KV
C111 "100nF" C0402_CAPC1005L 44.1,39.5 r180 top
C114 "100nF" C0402_CAPC1005L 41.95,39.5 r0 top
C115 "1314-Cap-0805-22uF/16V" C/0805 106.3,2.75 r180 top value=22uF/16V
C116 "1314-Cap-0805-22uF/16V" C/0805 93.45,15.9 r180 top value=22uF/16V
C117 "100nF" C0402_CAPC1005L 102.8,5.32 r180 bottom
C118 "100nF" C0402_CAPC1005L 91.7,17.7 r180 bottom
C119 "100nF" C0402_CAPC1005L 106.28,10.35 r180 top
C120 "100nF" C0402_CAPC1005L 95.288,22.784 r180 top
C121 "100nF" C0402_CAPC1005L 117.15,4.8 r270 bottom
C122 "100nF" C0402_CAPC1005L 106.05,17.2 r270 bottom
C123 "22uF/6.3V" C0402_CAPC1005L 104.212,22 r270 top
C124 "22uF/6.3V" C0402_CAPC1005L 115.3,9.6 r270 top
C125 "1314-Cap-0805-22uF/16V" C/0805 118.55,4.26 r90 bottom value=22uF/16V
C126 "1314-Cap-0805-22uF/16V" C/0805 107.6,16.65 r90 bottom value=22uF/16V
C127 "100nF" C0402_CAPC1005L 120.2,1.45 r0 bottom
C128 "100nF" C0402_CAPC1005L 108.75,15.15 r0 top
C129 "100nF" C0402_CAPC1005L 114.1,9.6 r90 top
C130 "100nF" C0402_CAPC1005L 103,22 r90 top
C131 "0346-Cap-0603-4.7nF" C/0603 109.55,23.8 r0 bottom value=4.7nF
C132 "0346-Cap-0603-4.7nF" C/0603 121.8,7.65 r90 bottom value=4.7nF
C133 "1646-Cap-0402-10uF/6.3V" C0402_CAPC1005L 47.55,19.45 r90 top value=10uF/6.3V
C134 "1006-Cap-0402-1uF/6V3" C0402_CAPC1005L 50.95,23.75 r0 top value=1uF/6.3V
C135 "1646-Cap-0402-10uF/6.3V" C0402_CAPC1005L 52.325,21.825 r270 top value=10uF/6.3V
C136 "1006-Cap-0402-1uF/6V3" C0402_CAPC1005L 46.7,19.45 r90 top value=1uF/6.3V
C137 "1006-Cap-0402-1uF/6V3" C0402_CAPC1005L 53.674,26.818 r270 top value=1uF/6.3V
C138 "1006-Cap-0402-1uF/6V3" C0402_CAPC1005L 48.25,29.4 r270 top value=1uF/6.3V
C139 "0321-Cap-0402-18pF/50V" C0402_CAPC1005L 40.5,21.4 r180 bottom value=18pF
C140 "1006-Cap-0402-1uF/6V3" C0402_CAPC1005L 48,26.125 r90 top value=1uF/6.3V
C141 "1006-Cap-0402-1uF/6V3" C0402_CAPC1005L 43.275,27.403 r0 top value=1uF/6.3V
C142 "0321-Cap-0402-18pF/50V" C0402_CAPC1005L 41.3,26.7 r0 bottom value=18pF
C143 "1646-Cap-0402-10uF/6.3V" C0402_CAPC1005L 45.45,22.25 r0 top value=10uF/6.3V
C144 "1006-Cap-0402-1uF/6V3" C0402_CAPC1005L 51.4,21.825 r270 top value=1uF/6.3V
C145 "100nF" C0402_CAPC1005L 50.95,24.6 r0 top
C146 "1006-Cap-0402-1uF/6V3" C0402_CAPC1005L 45.45,21.4 r0 top value=1uF/6.3V
C147 "100nF" C0402_CAPC1005L 44.1,24.3 r0 top
C148 "100nF" C0402_CAPC1005L 48.95,19.45 r90 top
C149 "1006-Cap-0402-1uF/6V3" C0402_CAPC1005L 50.5,22 r270 top value=1uF/6.3V
C150 "100nF" C0402_CAPC1005L 46.6,26.15 r90 top
C151 "100nF" C0402_CAPC1005L 49.1,29.4 r270 top
C152 "100nF" C0402_CAPC1005L 49.8,20.1 r90 top
C153 "100nF" C0402_CAPC1005L 52.874,26.818 r270 top
C154 "100nF" C0402_CAPC1005L 43.275,26.503 r0 top
C155 "100nF" C0402_CAPC1005L 48.45,21.4 r0 top
C156 "0958-Cap-0603-30pF/50V" C/0603 41.4,17.8 r0 bottom value=30pF
C157 "100nF" C0402_CAPC1005L 20.2,29.3 r90 top
C158 "22uF/6.3V" C0402_CAPC1005L 58.9,28.595 r180 bottom
C159 "22uF/6.3V" C0402_CAPC1005L 65.77,29.38 r270 bottom
C160 "100nF" C0402_CAPC1005L 43.75,19.3 r90 top
C161 "1006-Cap-0402-1uF/6V3" C0402_CAPC1005L 19.35,29.3 r90 top value=1uF/6.3V
C162 "1006-Cap-0402-1uF/6V3" C0402_CAPC1005L 44.575,19.303 r90 top value=1uF/6.3V
C163 "0567-Cap-1206-1nF/2KV" C/1206 49.85,8.4 r90 bottom value=1nF/2KV
C164 "1646-Cap-0402-10uF/6.3V" C0402_CAPC1005L 45.424,19.303 r90 top value=10uF/6.3V
C165 "22uF/6.3V" C0402_CAPC1005L 58.9,20.15 r180 bottom
C166 "22uF/6.3V" C0402_CAPC1005L 65.25,19.8 r0 bottom
C167 "100nF" C0402_CAPC1005L 57.525,100.675 r90 top
C168 "330uF/6.3V" CAN-SMD-D630 29.4,49.35 r270 top
C169 "330uF/6.3V" CAN-SMD-D630 22.3,49.35 r270 top
C170 "100nF" C0402_CAPC1005L 51.7,79.5 r180 bottom
C171 "100nF" C0402_CAPC1005L 40.7,79.4 r180 bottom
C172 "100nF" C0402_CAPC1005L 45.5,91.5 r0 bottom
C173 "100nF" C0402_CAPC1005L 51.95,98.85 r90 top
C174 "22uF/6.3V" C0402_CAPC1005L 37.29,45.25 r0 top
C175 "100nF" C0402_CAPC1005L 29.9,79.7 r0 bottom
C176 "22uF/6.3V" C0402_CAPC1005L 40.865,46.8 r90 top
C177 "0958-Cap-0603-30pF/50V" C/0603 21.55,82.65 r0 bottom value=30pF
C178 "0958-Cap-0603-30pF/50V" C/0603 21.55,84.1 r0 bottom value=30pF
C179 "0958-Cap-0603-30pF/50V" C/0603 21.55,85.55 r0 bottom value=30pF
C180 "22uF/6.3V" C0402_CAPC1005L 38.65,54.55 r180 top
C181 "22uF/6.3V" C0402_CAPC1005L 16.75,29.65 r180 bottom
C182 "100nF" C0402_CAPC1005L 10.2,30.15 r270 bottom
C183 "1602-Cap-0402-100pF" C0402_CAPC1005L 114.85,53.85 r180 bottom value=100pF
C184 "1602-Cap-0402-100pF" C0402_CAPC1005L 114.325,76.921 r180 bottom value=100pF
C185 "100nF" C0402_CAPC1005L 105.8,54.3 r0 bottom
C186 "100nF" C0402_CAPC1005L 105.95,64.7 r90 bottom
C187 "100nF" C0402_CAPC1005L 105.8,77.65 r0 bottom
C188 "100nF" C0402_CAPC1005L 105.95,88.05 r90 bottom
C189 "1602-Cap-0402-100pF" C0402_CAPC1005L 110.2,95.35 r180 bottom value=100pF
C190 "1602-Cap-0402-100pF" C0402_CAPC1005L 110.26,72.015 r180 bottom value=100pF
C191 "1314-Cap-0805-22uF/16V" C/0805 110.25,68.5 r90 bottom value=22uF/16V
C192 "1314-Cap-0805-22uF/16V" C/0805 110.2,91.903 r90 bottom value=22uF/16V
C193 "100nF" C0402_CAPC1005L 108.6,92.403 r270 bottom
C194 "100nF" C0402_CAPC1005L 108.66,69.043 r270 bottom
C195 "100nF" C0402_CAPC1005L 106.95,64.7 r270 bottom
C196 "100nF" C0402_CAPC1005L 104.95,88.05 r270 bottom
C197 "100nF" C0402_CAPC1005L 104.95,64.7 r270 bottom
C198 "100nF" C0402_CAPC1005L 106.95,88.05 r270 bottom
C199 "100nF" C0402_CAPC1005L 107.75,64.7 r270 bottom
C200 "1314-Cap-0805-22uF/16V" C/0805 106.029,68.318 r180 bottom value=22uF/16V
C201 "100nF" C0402_CAPC1005L 107.75,88.05 r270 bottom
C202 "1314-Cap-0805-22uF/16V" C/0805 106,91.653 r180 bottom value=22uF/16V
C203 "100nF" C0402_CAPC1005L 105.743,53.165 r180 bottom
C204 "100nF" C0402_CAPC1005L 105.7,76.3 r180 bottom
C205 "100nF" C0402_CAPC1005L 105.257,66.69 r0 bottom
C206 "100nF" C0402_CAPC1005L 105.2,90.053 r0 bottom
C207 "100nF" C0402_CAPC1005L 90.8,53 r0 bottom
C208 "100nF" C0402_CAPC1005L 93,74.853 r0 bottom
C209 "100nF" C0402_CAPC1005L 85,49.845 r180 bottom
C210 "100nF" C0402_CAPC1005L 90.9,64.2 r180 bottom
C211 "100nF" C0402_CAPC1005L 91.1,87.553 r180 bottom
C212 "1314-Cap-0805-22uF/16V" C/0805 90.379,66.818 r0 bottom value=22uF/16V
C213 "100nF" C0402_CAPC1005L 60.95,60.7 r0 bottom
C214 "1314-Cap-0805-22uF/16V" C/0805 90.3,90.053 r0 bottom value=22uF/16V
C215 "100nF" C0402_CAPC1005L 62.8,62.3 r270 bottom
C216 "100nF" C0402_CAPC1005L 88.8,46.4 r0 bottom
C217 "1314-Cap-0805-22uF/16V" C/0805 91,27.7 r0 bottom value=22uF/16V
C218 "100nF" C0402_CAPC1005L 91.45,30.25 r180 bottom
C219 "100nF" C0402_CAPC1005L 93.922,30.785 r180 top
C220 "100nF" C0402_CAPC1005L 93.822,36.585 r180 top
C221 "100nF" C0402_CAPC1005L 103.3,32.25 r90 top
C222 "100nF" C0402_CAPC1005L 103.522,36.063 r270 top
C223 "100nF" C0402_CAPC1005L 106.45,30.988 r270 bottom
C224 "1314-Cap-0805-22uF/16V" C/0805 108,36 r180 bottom value=22uF/16V
C225 "100nF" C0402_CAPC1005L 107.95,32.8 r270 top
C226 "1314-Cap-0805-22uF/16V" C/0805 91.3,39.468 r0 bottom value=22uF/16V
C227 "100nF" C0402_CAPC1005L 92,42.007 r180 bottom
C228 "100nF" C0402_CAPC1005L 96.3,50.55 r90 top
C229 "100nF" C0402_CAPC1005L 94.594,44.424 r90 top
C230 "100nF" C0402_CAPC1005L 106.1,42.168 r0 bottom
C231 "100nF" C0402_CAPC1005L 104.1,48.768 r0 top
C232 "100nF" C0402_CAPC1005L 106.113,43.368 r0 bottom
C233 "1314-Cap-0805-22uF/16V" C/0805 108.038,40.368 r180 bottom value=22uF/16V
C234 "0124-Cap-0603-1uF/25V" C/0603 113.2,44.718 r270 top value=1uF/25V
C235 "0124-Cap-0603-1uF/25V" C/0603 113.2,48.018 r270 top value=1uF/25V
C236 "0124-Cap-0603-1uF/25V" C/0603 108.05,48.768 r0 top value=1uF/25V
C237 "0124-Cap-0603-1uF/25V" C/0603 106.1,41.368 r180 top value=1uF/25V
C238 "0124-Cap-0603-1uF/25V" C/0603 109.9,41.368 r0 top value=1uF/25V
C239 "22uF/6.3V" C0402_CAPC1005L 13.175,97.547 r0 bottom
C240 "1314-Cap-0805-22uF/16V" C/0805 12.525,99.45 r0 bottom value=22uF/16V
C241 "22uF/6.3V" C0402_CAPC1005L 2.611,95.6 r270 bottom
C242 "22uF/6.3V" C0402_CAPC1005L 22.875,98.95 r270 bottom
C243 "22uF/6.3V" C0402_CAPC1005L 7.55,93.528 r180 bottom
C244 "100nF" C0402_CAPC1005L 4.55,93.528 r0 bottom
C245 "100nF" C0402_CAPC1005L 11.8,88.528 r0 top
C246 "100nF" C0402_CAPC1005L 9.35,89.328 r180 top
C247 "100nF" C0402_CAPC1005L 9.35,86.128 r180 top
C248 "100nF" C0402_CAPC1005L 9.35,88.528 r180 top
C249 "100nF" C0402_CAPC1005L 9.35,86.928 r180 top
C250 "100nF" C0402_CAPC1005L 9.35,90.928 r180 top
C251 "100nF" C0402_CAPC1005L 9.35,87.728 r180 top
C252 "100nF" C0402_CAPC1005L 9.35,90.128 r180 top
C253 "22uF/6.3V" C0402_CAPC1005L 18.711,23.95 r270 bottom
C254 "100nF" C0402_CAPC1005L 31,17 r180 bottom
C255 "330uF/6.3V" CAN-SMD-D630 18.7,19.25 r90 top
C256 "100nF" C0402_CAPC1005L 34.95,16.35 r180 bottom
C257 "0567-Cap-1206-1nF/2KV" C/1206 31.05,5.2 r90 bottom value=1nF/2KV
C258 "100nF" C0402_CAPC1005L 17.45,19.2 r270 bottom
C259 "100nF" C0402_CAPC1005L 31,17.8 r180 bottom
C260 "100nF" C0402_CAPC1005L 34.95,17.15 r180 bottom
D1 "SMAJ33CA" SMAJ_TRANSIL 86.465,7.9 r180 top
D2 "SK510A" SMAJ 80.95,12.25 r90 top
D3 "DT12A120P5-13" POWERDI-5_DIO 81.7,48.654 r270 top
D4 "Status" LED-SMT-0603_APT1608CGCK 82.4,21.3 r180 top
D5 "ASMB-LTC3-0D335" 4-PLCC_LED_2121_BROADCOM 8.55,18.975 r180 top
D6 "Status" LED-SMT-0603_APT1608CGCK 49,102.6 r270 top
D7 "ASMB-LTC3-0D335" 4-PLCC_LED_2121_BROADCOM 8.55,9.875 r0 top
D8 "ASMB-LTC3-0D335" 4-PLCC_LED_2121_BROADCOM 8.55,14.425 r0 top
D9 "ASMB-LTC3-0D335" 4-PLCC_LED_2121_BROADCOM 8.55,23.525 r0 top
D10 "Status" LED-SMT-0603_APT1608CGCK 62.047,88.749 r180 bottom
D11 "Status" LED-SMT-0603_APT1608CGCK 62.047,94.349 r180 bottom
D12 "Status" LED-SMT-0603_APT1608CGCK 62.147,78.049 r180 bottom
D13 "Status" LED-SMT-0603_APT1608CGCK 62.047,83.449 r180 bottom
D14 "SMAJ33CA" SMAJ_TRANSIL 126.85,59.25 r270 bottom
D15 "SMAJ33CA" SMAJ_TRANSIL 126.85,65.85 r270 bottom
D16 "SMAJ33CA" SMAJ_TRANSIL 126.85,72.45 r270 bottom
D17 "SMAJ33CA" SMAJ_TRANSIL 126.85,79 r270 bottom
D18 "Status" LED-SMT-0603_APT1608CGCK 43,102.6 r270 top
D19 "BAV199" SOT23_M 47.6,46.5 r270 top
D20 "Status" LED-SMT-0603_APT1608CGCK 44.5,102.6 r270 top
D21 "Status" LED-SMT-0603_APT1608CGCK 46,102.6 r270 top
D22 "Status" LED-SMT-0603_APT1608CGCK 47.5,102.6 r270 top
D23 "SMAJ33CA" SMAJ_TRANSIL 126.85,85.25 r90 bottom
D24 "SMAJ33CA" SMAJ_TRANSIL 113.054,66.718 r90 bottom
D25 "SMAJ33CA" SMAJ_TRANSIL 113,90.053 r90 bottom
D26 "SMAJ33CA" SMAJ_TRANSIL 125,96.45 r180 bottom
D27 "SMAJ33CA" SMAJ_TRANSIL 93.525,86.773 r270 top
D28 "SMAJ33CA" SMAJ_TRANSIL 86.575,86.723 r270 top
D29 "1N4148W" SOD123_ALT 91.93,81.948 r180 top
D30 "1N4148W" SOD123_ALT 85,81.925 r180 top
D31 "D5V0L1B2S9-7" SOD923_DIO 24.421,11.018 r90 bottom
D32 "D5V0L1B2S9-7" SOD923_DIO 9.15,50.543 r90 top
F1 "5A Slow" FUSC6125X279N 80.95,5.445 r90 top
FID1 "Fiducial round" FID_40X120_RND 121,102 r180 top locked
FID2 "Fiducial round" FID_40X120_RND 127,8 r180 top locked
FID3 "Fiducial round" FID_40X120_RND 2,10 r180 top locked
FID4 "Fiducial round" FID_40X120_RND 121,102 r0 bottom locked
FID5 "Fiducial round" FID_40X120_RND 127,8 r180 bottom locked
FID6 "Fiducial round" FID_40X120_RND 2,10 r180 bottom locked
H1 "Hole" MTG_HOLE_0.125#1 3,3 r0 top locked
H2 "Hole" MTG_HOLE_0.125#2 3.1,102 r0 top locked
H3 "Hole" MTG_HOLE_0.125#1 127,102 r0 top locked
H4 "Hole" MTG_HOLE_0.125#1 127,3 r0 top locked
H5 "Hole" MTG_HOLE_0.125#3 92.45,50.6 r0 top
J1 "000-Hdr-6pin" HDR1X6 20.48,103.05 r180 top
J2 "3210-16-001-12-00" CNC_CONN16_3210-16-001-12-00 58.44,53.14 r0 top locked
J3 "0395061002" Phoenix_1727566 92.2,4.469 r0 top locked
J4 "USB4105-GF-A-120" GCT_USB4105GFA120 4.972,47.85 r270 top
J5 "1728700000" WEIDMULLER_1728700000 121.95,73.75 r90 top locked
J6 "1728700000" WEIDMULLER_1728700000 121.95,31.25 r90 top locked
J7 "JXD0-0025NL" PULSE_JXD0-0025NL 48.935,9.684 r0 top locked
J8 "1775862-2" 17758622_FULL_SIZE 39.4,61 r0 bottom locked
J9 "SIM8055-6-1-14-00-A" SIM8055611400A 7.45,71.65 r90 bottom locked
J10 "JXD0-0025NL" PULSE_JXD0-0025NL 69.175,9.634 r0 top locked
J11 "1717832-2" MINI_PCIE_52PIN_CARD_LATCH_ALT 39.4,32.3 r0 bottom locked
J12 "MEM2052-00-195-00-A" MEM2051-00-195-00-A_REVC 8.4,33.6 r270 top locked
J13 "FTSH-105-01-L-DV-P-TR" SAMTEC_FTSH-105-01-L-DV-K-TR 21.35,34.95 r90 top
J14 "GRPB021VWVN-RC" CONN_WVN-RC_SUL 113.535,35.95 r0 top
J15 "F314-1A7H1-11034" AMPHENOL_F314-1A7H1-11034 5.481,83.728 r90 top
J16 "GSB4112312HR" "T_AMPHENOL_ GSB311231HR" 30.25,11.419 r0 top locked
J17 "000-Hdr-3pin" HDR1X3 19.1,54.9 r0 top
J18 "GRPB021VWVN-RC" CONN_WVN-RC_SUL 117.4,7.65 r270 top
J19 "GRPB021VWVN-RC" CONN_WVN-RC_SUL 120,7.65 r270 top
J20 "GRPB021VWVN-RC" CONN_WVN-RC_SUL 114.1,19.535 r270 top
J21 "GRPB021VWVN-RC" CONN_WVN-RC_SUL 111.7,19.535 r270 top
JP1 "Short" Short_040 114.6,62.05 r90 bottom
JP2 "Short" Short_040 114.4,85.3 r90 bottom
L2 "1641-Fer-1206-600ohm/2.5A" INDP1206 85.55,57.3 r180 top value=600ohm/2.5A
L3 "0405-Fer-0603-330ohm/1.7A" INDC1608x095 66.3,53.85 r90 bottom value="330 ohm/1.7A"
L4 "0405-Fer-0603-330ohm/1.7A" INDC1608x095 69.95,68.9 r180 bottom value="330 ohm/1.7A"
L5 "0405-Fer-0603-330ohm/1.7A" INDC1608x095 21.983,27.984 r270 top value="330 ohm/1.7A"
L6 "0405-Fer-0603-330ohm/1.7A" INDC1608x095 33.65,47.89 r270 top value="330 ohm/1.7A"
L7 "0405-Fer-0603-330ohm/1.7A" INDC1608x095 29.243,34.95 r180 top value="330 ohm/1.7A"
L8 "1641-Fer-1206-600ohm/2.5A" INDP1206 84.591,78.296 r270 top value=600ohm/2.5A
L9 "1641-Fer-1206-600ohm/2.5A" INDP1206 59.925,47.9 r0 top value=600ohm/2.5A
L10 "1641-Fer-1206-600ohm/2.5A" INDP1206 84.45,27.4 r180 top value=600ohm/2.5A
L11 "NS10165T4R7NNA" INDC3225N 89.748,72.046 r0 top value=1uH/5.5A
L12 "60 ohm/15A" COMMON_CHOKE_Laird_CM3421Y600R-10 95.8,9.3 r0 top
L13 "BMRA000606304R7MA1" INDP_7.3X6.6N 66.425,29 r0 top value=4.7uH/5.5A
L14 "DR127-150-R" EATON_DR127 72.7,42.978 r270 top value=15uH/5A
L15 "0405-Fer-0603-330ohm/1.7A" INDC1608x095 8.85,33 r270 bottom value="330 ohm/1.7A"
L16 "0405-Fer-0603-330ohm/1.7A" INDC1608x095 18.95,46.95 r180 bottom value="330 ohm/1.7A"
L17 "0405-Fer-0603-330ohm/1.7A" INDC1608x095 4.85,33 r90 bottom value="330 ohm/1.7A"
L18 "90 ohm/0.4A" COMMON_CHOKE_BOURNS_SRF2012-900YA 12.525,51.475 r90 bottom
L24 "0405-Fer-0603-330ohm/1.7A" INDC1608x095 102.95,10.6 r270 top value="330 ohm/1.7A"
L25 "0405-Fer-0603-330ohm/1.7A" INDC1608x095 95,23.9 r0 top value="330 ohm/1.7A"
L26 "0405-Fer-0603-330ohm/1.7A" INDC1608x095 63.55,28.91 r0 bottom value="330 ohm/1.7A"
L27 "0405-Fer-0603-330ohm/1.7A" INDC1608x095 32.75,55.054 r180 top value="330 ohm/1.7A"
L28 "0405-Fer-0603-330ohm/1.7A" INDC1608x095 32.75,53.654 r180 top value="330 ohm/1.7A"
L29 "0405-Fer-0603-330ohm/1.7A" INDC1608x095 58.65,100.4 r90 top value="330 ohm/1.7A"
L30 "0405-Fer-0603-330ohm/1.7A" INDC1608x095 50.8,99.65 r270 top value="330 ohm/1.7A"
L31 "0405-Fer-0603-330ohm/1.7A" INDC1608x095 14.8,31.05 r180 bottom value="330 ohm/1.7A"
L32 "0405-Fer-0603-330ohm/1.7A" INDC1608x095 87.675,93.433 r270 top value="330 ohm/1.7A"
L33 "0405-Fer-0603-330ohm/1.7A" INDC1608x095 12.825,96.15 r0 bottom value="330 ohm/1.7A"
L34 "0405-Fer-0603-330ohm/1.7A" INDC1608x095 1.05,95.89 r270 bottom value="330 ohm/1.7A"
L35 "12 ohm/0.1A" COIL0302 17.15,72.8 r0 top
L36 "12 ohm/0.1A" COIL0302 20.45,72.8 r0 top
L37 "12 ohm/0.1A" COIL0302 15.5,72.775 r0 top
L38 "12 ohm/0.1A" COIL0302 18.8,72.8 r0 top
L39 "12 ohm/0.1A" COIL0302 22.1,72.8 r0 top
L40 "0405-Fer-0603-330ohm/1.7A" INDC1608x095 20.311,24.1 r270 bottom value="330 ohm/1.7A"
LBL1 "SN Label 10x10mm" LABEL_10x10mm_ALT 68.55,44.05 r0 bottom
LBL2 "SN Label 0.25x0.9 inch" LABEL_0.25x0.9IN 99.75,97.65 r0 top
LP1 "LPF-S014331S" LPF-S014331S 8.55,16.165 r270 top
M1 "2309409-2" CON-TE-2309409-2_TORADEX_VERDIN_MTG_rev2 45.625,74.95 r180 top locked
ME1 "9774070243R" "MTG_POST WURTH 774070243" 85.625,61.5 r0 top
ME2 "9774070243R" "MTG_POST WURTH 774070243" 5.625,61.5 r0 top
ME3 "9774025243R" WURTH_9774025243R 12.925,92.504 r0 top
ME4 "9774025243R" WURTH_9774025243R 78.325,92.5 r0 top
MECH1 "MECH-Toradex_Logo" T_TORADEX_LOGO 78.957,102.341 r0 top
PR1 "TLP241A" TLP241A_TP1 69.9,76.2 r0 bottom
PR2 "TLP241A" TLP241A_TP1 69.9,81.54 r0 bottom
PR3 "TLP241A" TLP241A_TP1 69.9,86.84 r0 bottom
PR4 "TLP241A" TLP241A_TP1 69.9,92.2 r0 bottom
PTC1 "H:0.1A, T:0.3A, 60V" PTC_1812 78.25,86.4 r90 bottom
PTC2 "H:0.1A, T:0.3A, 60V" PTC_1812 82.25,86.4 r90 bottom
PTC3 "H:0.1A, T:0.3A, 60V" PTC_1812 82.9,102 r0 bottom
PTC4 "H:0.1A, T:0.3A, 60V" PTC_1812 82.9,98 r0 bottom
PTC5 "H:0.1A, T:0.3A, 60V" PTC_1812 109.5,61 r180 top
PTC6 "H:0.1A, T:0.3A, 60V" PTC_1812 109.5,84.2 r180 top
PTC7 "H:0.1A, T:0.3A, 60V" PTC_1812 94.55,102.3 r0 top
PTC8 "H:0.1A, T:0.3A, 60V" PTC_1812 94.55,102.3 r0 bottom
Q1 "NTZD3154" SOT563 2.75,22.8 r270 bottom
Q2 "NTZD3154" SOT563 4.95,22.8 r270 bottom
Q3 "NTZD3154" SOT563 12.614,22.815 r270 bottom
Q4 "NTZD3154" SOT563 15.214,22.815 r270 bottom
Q5 "FDV301N" SOT23 58.347,75.949 r90 bottom
Q6 "FDV301N" SOT23 58.247,81.349 r90 bottom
